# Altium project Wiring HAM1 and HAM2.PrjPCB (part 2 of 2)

## Sheet JMX_PM1.SchDoc: JM1, JM2, JM3 & PM1
size C; Organization: LIGO Laboratory; Address1: California Institute of Technology; Address2: Massachusetts Institute of Technology; DocumentNumber: D0902810; Revision: v11; SheetNumber: 9; SheetTotal: 14; Engineer: J.Kissel/L.Sánchez
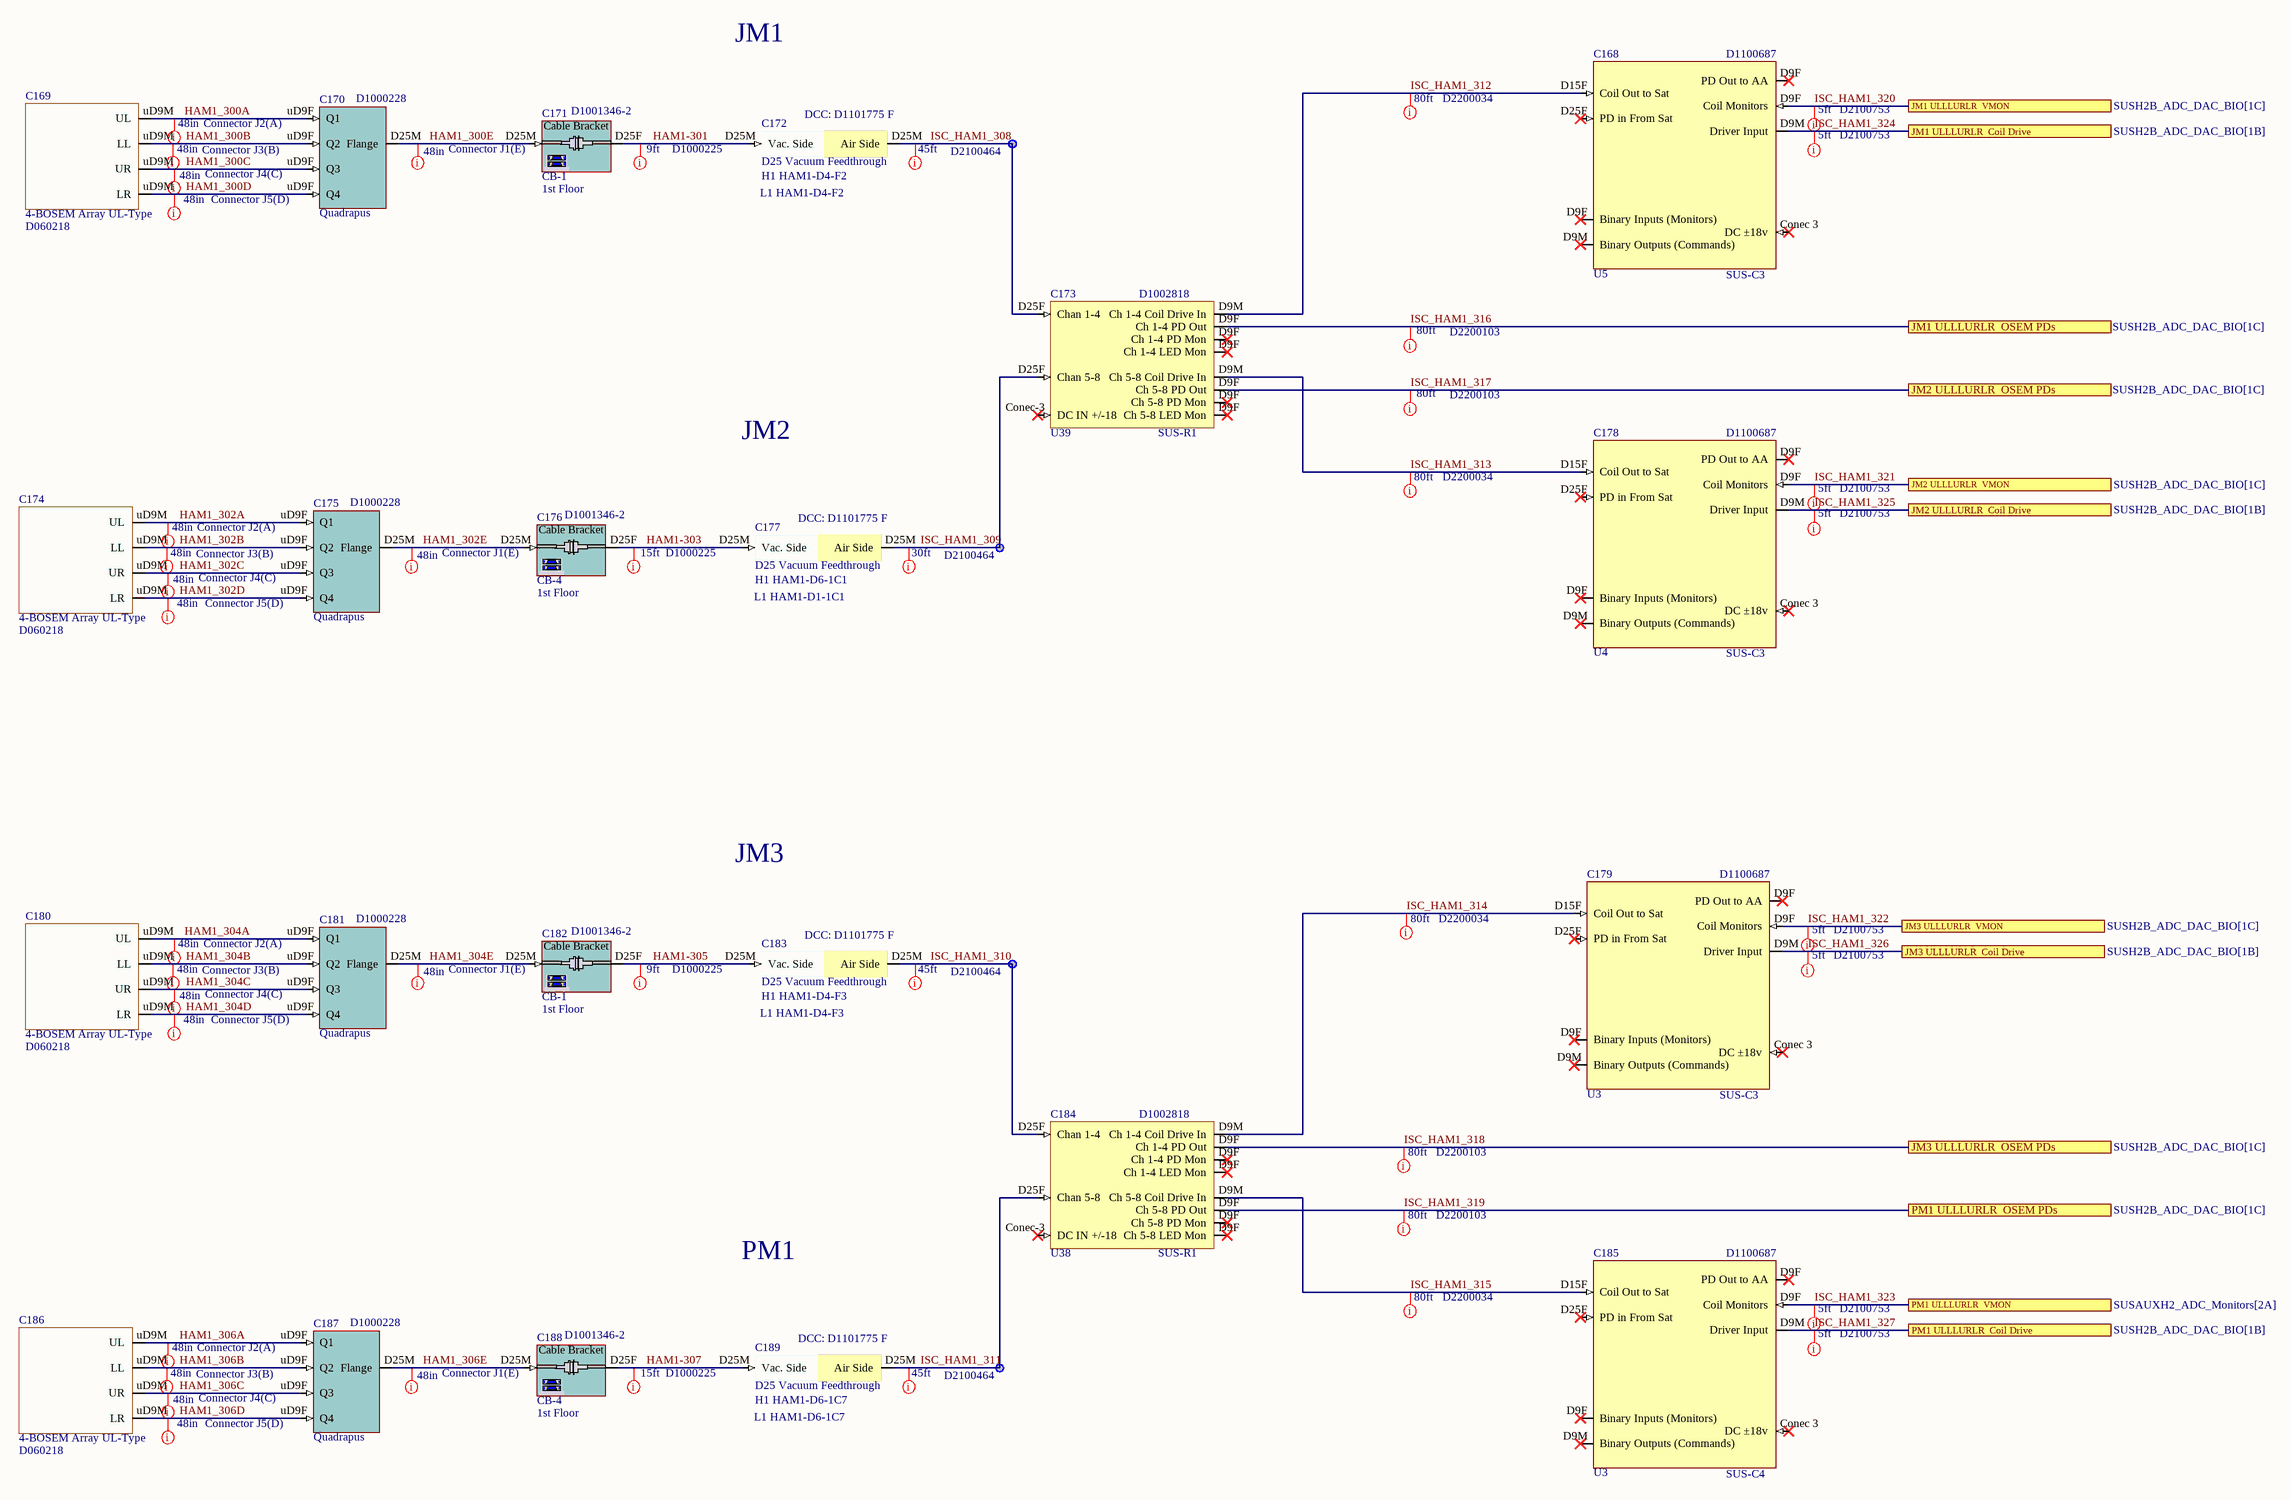
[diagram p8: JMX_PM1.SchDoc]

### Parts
C168  Slot: U5  Rack: SUS-C3  DCC: D1100687  (hidden comment: CD HAM-A D1100687)
C169  4-BOSEM Array UL-Type  DCC: D060218
C170  Quadrapus  DCC: D1000228
C171  Rack: CB-1  Slot: 1st Floor  DCC: D1001346-2  (hidden comment: Cable Bracket)
C172  D25 Vacuum Feedthrough  value H1 HAM1-D4-F2  DCC: D1101775 F
C173  DCC: D1002818  Rack: SUS-R1  Slot: U39  (hidden comment: Satellite Amplifier US D1002818 Dual)
C174  4-BOSEM Array UL-Type  DCC: D060218
C175  Quadrapus  DCC: D1000228
C176  Rack: CB-4  Slot: 1st Floor  DCC: D1001346-2  (hidden comment: Cable Bracket)
C177  D25 Vacuum Feedthrough  value H1 HAM1-D6-1C1  DCC: D1101775 F
C178  Slot: U4  Rack: SUS-C3  DCC: D1100687  (hidden comment: CD HAM-A D1100687)
C179  Slot: U3  Rack: SUS-C3  DCC: D1100687  (hidden comment: CD HAM-A D1100687)
C180  4-BOSEM Array UL-Type  DCC: D060218
C181  Quadrapus  DCC: D1000228
C182  Rack: CB-1  Slot: 1st Floor  DCC: D1001346-2  (hidden comment: Cable Bracket)
C183  D25 Vacuum Feedthrough  value H1 HAM1-D4-F3  DCC: D1101775 F
C184  DCC: D1002818  Rack: SUS-R1  Slot: U38  (hidden comment: Satellite Amplifier US D1002818 Dual)
C185  Slot: U3  Rack: SUS-C4  DCC: D1100687  (hidden comment: CD HAM-A D1100687)
C186  4-BOSEM Array UL-Type  DCC: D060218
C187  Quadrapus  DCC: D1000228
C188  Rack: CB-4  Slot: 1st Floor  DCC: D1001346-2  (hidden comment: Cable Bracket)
C189  D25 Vacuum Feedthrough  value H1 HAM1-D6-1C7  DCC: D1101775 F

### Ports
JM1 ULLLURLR  Coil Drive (see SUSH2B_ADC_DAC_BIO[1B]), JM1 ULLLURLR  OSEM PDs (see SUSH2B_ADC_DAC_BIO[1C]), JM1 ULLLURLR  VMON (see SUSH2B_ADC_DAC_BIO[1C]), JM2 ULLLURLR  Coil Drive (see SUSH2B_ADC_DAC_BIO[1B]), JM2 ULLLURLR  OSEM PDs (see SUSH2B_ADC_DAC_BIO[1C]), JM2 ULLLURLR  VMON (see SUSH2B_ADC_DAC_BIO[1C]), JM3 ULLLURLR  Coil Drive (see SUSH2B_ADC_DAC_BIO[1B]), JM3 ULLLURLR  OSEM PDs (see SUSH2B_ADC_DAC_BIO[1C]), JM3 ULLLURLR  VMON (see SUSH2B_ADC_DAC_BIO[1C]), PM1 ULLLURLR  Coil Drive (see SUSH2B_ADC_DAC_BIO[1B]), PM1 ULLLURLR  OSEM PDs (see SUSH2B_ADC_DAC_BIO[1C]), PM1 ULLLURLR  VMON (see SUSAUXH2_ADC_Monitors[2A])

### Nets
HAM1-301: C171.D25F C172.D25M(Vac._Side)
HAM1-303: C176.D25F C177.D25M(Vac._Side)
HAM1-305: C182.D25F C183.D25M(Vac._Side)
HAM1-307: C188.D25F C189.D25M(Vac._Side)
HAM1_300A: C169.uD9M(UL) C170.uD9F(Q1)
HAM1_300B: C169.uD9M(LL) C170.uD9F(Q2)
HAM1_300C: C169.uD9M(UR) C170.uD9F(Q3)
HAM1_300D: C169.uD9M(LR) C170.uD9F(Q4)
HAM1_300E: C170.D25M(Flange) C171.D25M
HAM1_302A: C174.uD9M(UL) C175.uD9F(Q1)
HAM1_302B: C174.uD9M(LL) C175.uD9F(Q2)
HAM1_302C: C174.uD9M(UR) C175.uD9F(Q3)
HAM1_302D: C174.uD9M(LR) C175.uD9F(Q4)
HAM1_302E: C175.D25M(Flange) C176.D25M
HAM1_304A: C180.uD9M(UL) C181.uD9F(Q1)
HAM1_304B: C180.uD9M(LL) C181.uD9F(Q2)
HAM1_304C: C180.uD9M(UR) C181.uD9F(Q3)
HAM1_304D: C180.uD9M(LR) C181.uD9F(Q4)
HAM1_304E: C181.D25M(Flange) C182.D25M
HAM1_306A: C186.uD9M(UL) C187.uD9F(Q1)
HAM1_306B: C186.uD9M(LL) C187.uD9F(Q2)
HAM1_306C: C186.uD9M(UR) C187.uD9F(Q3)
HAM1_306D: C186.uD9M(LR) C187.uD9F(Q4)
HAM1_306E: C187.D25M(Flange) C188.D25M
ISC_HAM1_308: C172.D25M(Air_Side) C173.D25F(Chan_1-4)
ISC_HAM1_309: C173.D25F(Chan_5-8) C177.D25M(Air_Side)
ISC_HAM1_310: C183.D25M(Air_Side) C184.D25F(Chan_1-4)
ISC_HAM1_311: C184.D25F(Chan_5-8) C189.D25M(Air_Side)
ISC_HAM1_312: C168.D15F(Coil_Out_to_Sat) C173.D9M(Ch_1-4_Coil_Drive_In)
ISC_HAM1_313: C173.D9M(Ch_5-8_Coil_Drive_In) C178.D15F(Coil_Out_to_Sat)
ISC_HAM1_314: C179.D15F(Coil_Out_to_Sat) C184.D9M(Ch_1-4_Coil_Drive_In)
ISC_HAM1_315: C184.D9M(Ch_5-8_Coil_Drive_In) C185.D15F(Coil_Out_to_Sat)
ISC_HAM1_316: C173.D9F(Ch_1-4_PD_Out) ; port JM1 ULLLURLR  OSEM PDs
ISC_HAM1_317: C173.D9F(Ch_5-8_PD_Out) ; port JM2 ULLLURLR  OSEM PDs
ISC_HAM1_318: C184.D9F(Ch_1-4_PD_Out) ; port JM3 ULLLURLR  OSEM PDs
ISC_HAM1_319: C184.D9F(Ch_5-8_PD_Out) ; port PM1 ULLLURLR  OSEM PDs
ISC_HAM1_320: C168.D9F(PD_Out_to_AA) ; port JM1 ULLLURLR  VMON
ISC_HAM1_321: C178.D9F(PD_Out_to_AA) ; port JM2 ULLLURLR  VMON
ISC_HAM1_322: C179.D9F(PD_Out_to_AA) ; port JM3 ULLLURLR  VMON
ISC_HAM1_323: C185.D9F(PD_Out_to_AA) ; port PM1 ULLLURLR  VMON
ISC_HAM1_324: C168.D9M(Binary_Outputs_(Commands)) ; port JM1 ULLLURLR  Coil Drive
ISC_HAM1_325: C178.D9M(Binary_Outputs_(Commands)) ; port JM2 ULLLURLR  Coil Drive
ISC_HAM1_326: C179.D9M(Binary_Outputs_(Commands)) ; port JM3 ULLLURLR  Coil Drive
ISC_HAM1_327: C185.D9M(Binary_Outputs_(Commands)) ; port PM1 ULLLURLR  Coil Drive

Not connected (* = marked no-connect by the designer): C168 Conec 3(DC_±18v)* D25F(PD_in_From_Sat)*; C173 Conec-3(DC_IN_+/-18)*; C178 Conec 3(DC_±18v)* D25F(PD_in_From_Sat)*; C179 Conec 3(DC_±18v)* D25F(PD_in_From_Sat)*; C184 Conec-3(DC_IN_+/-18)*; C185 Conec 3(DC_±18v)* D25F(PD_in_From_Sat)*

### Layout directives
Length: 45ft; DCC: D2100464: ISC_HAM1_308, ISC_HAM1_310, ISC_HAM1_311
Length: 5ft; DCC: D2100753: ISC_HAM1_320, ISC_HAM1_321, ISC_HAM1_322, ISC_HAM1_323, ISC_HAM1_324, ISC_HAM1_325, ISC_HAM1_326, ISC_HAM1_327
Length: 48in; DCC: Connector J5(D): HAM1_300D, HAM1_302D, HAM1_304D, HAM1_306D
Length: 48in; DCC: Connector J4(C): HAM1_300C, HAM1_302C, HAM1_304C, HAM1_306C
Length: 48in; DCC: Connector J3(B): HAM1_300B, HAM1_302B, HAM1_304B, HAM1_306B
Length: 48in; DCC: Connector J2(A): HAM1_300A, HAM1_302A, HAM1_304A, HAM1_306A
Length: 80ft; DCC: D2200034: ISC_HAM1_312, ISC_HAM1_313, ISC_HAM1_314, ISC_HAM1_315
Length: 48in; DCC: Connector J1(E): HAM1_300E, HAM1_302E, HAM1_304E, HAM1_306E
Length: 9ft; DCC: D1000225: HAM1-301, HAM1-305
Length: 30ft; DCC: D2100464: ISC_HAM1_309
Length: 15ft; DCC: D1000225: HAM1-303, HAM1-307
Length: 80ft; DCC: D2200103: ISC_HAM1_316, ISC_HAM1_317, ISC_HAM1_318, ISC_HAM1_319

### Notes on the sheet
- JM1
- (near C172) L1 HAM1-D4-F2
- JM2
- (near C177) L1 HAM1-D1-1C1
- JM3
- (near C183) L1 HAM1-D4-F3
- PM1
- (near C189) L1 HAM1-D6-1C7

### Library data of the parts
C168 C178 C179 C185 = CD HAM-A D1100687: System: SUS; Serial: Sxxxxxxx
C169 C174 C180 C186 = 4-BOSEM Array UL-Type: Rack: R?; Slot: U?; Serial: Sxxxxxxx; System: SUS
C170 C175 C181 C187 = D1000228 D25 Quadrapus: Slot: U?; Rack: R?; Serial: Sxxxxxxx; System: SUS
C171 C176 C182 C188 = D1001346-2 1st Cable Bracket: D1001346-2 1/2 Cable Bracket for HAM Tables; Serial: Sxxxxxxx; System: SUS
C172 = VacFeedD25: Serial: Sxxxxxxx; System: ISC; Rack: HAM1; Slot: D4-F2
C173 C184 = Satellite Amplifier US D1002818: Serial: Sxxxxxxx
C177 = VacFeedD25: Serial: Sxxxxxxx; System: ISC; Rack: HAM1; Slot: D1-1C3
C183 = VacFeedD25: Serial: Sxxxxxxx; System: ISC; Rack: HAM1; Slot: D4-F3
C189 = VacFeedD25: Serial: Sxxxxxxx; System: ISC; Rack: HAM1; Slot: D4-F1

## Sheet SUSH2A_ADC_DAC_BIO.SchDoc: SUSH2A_ADC_DAC_BIO
size C; Organization: LIGO Laboratory; Address1: California Institute of Technology; Address2: Massachusetts Institute of Technology; DocumentNumber: D0902810; Revision: v11; SheetNumber: 10; SheetTotal: 14; Engineer: J.Kissel/L.Sánchez
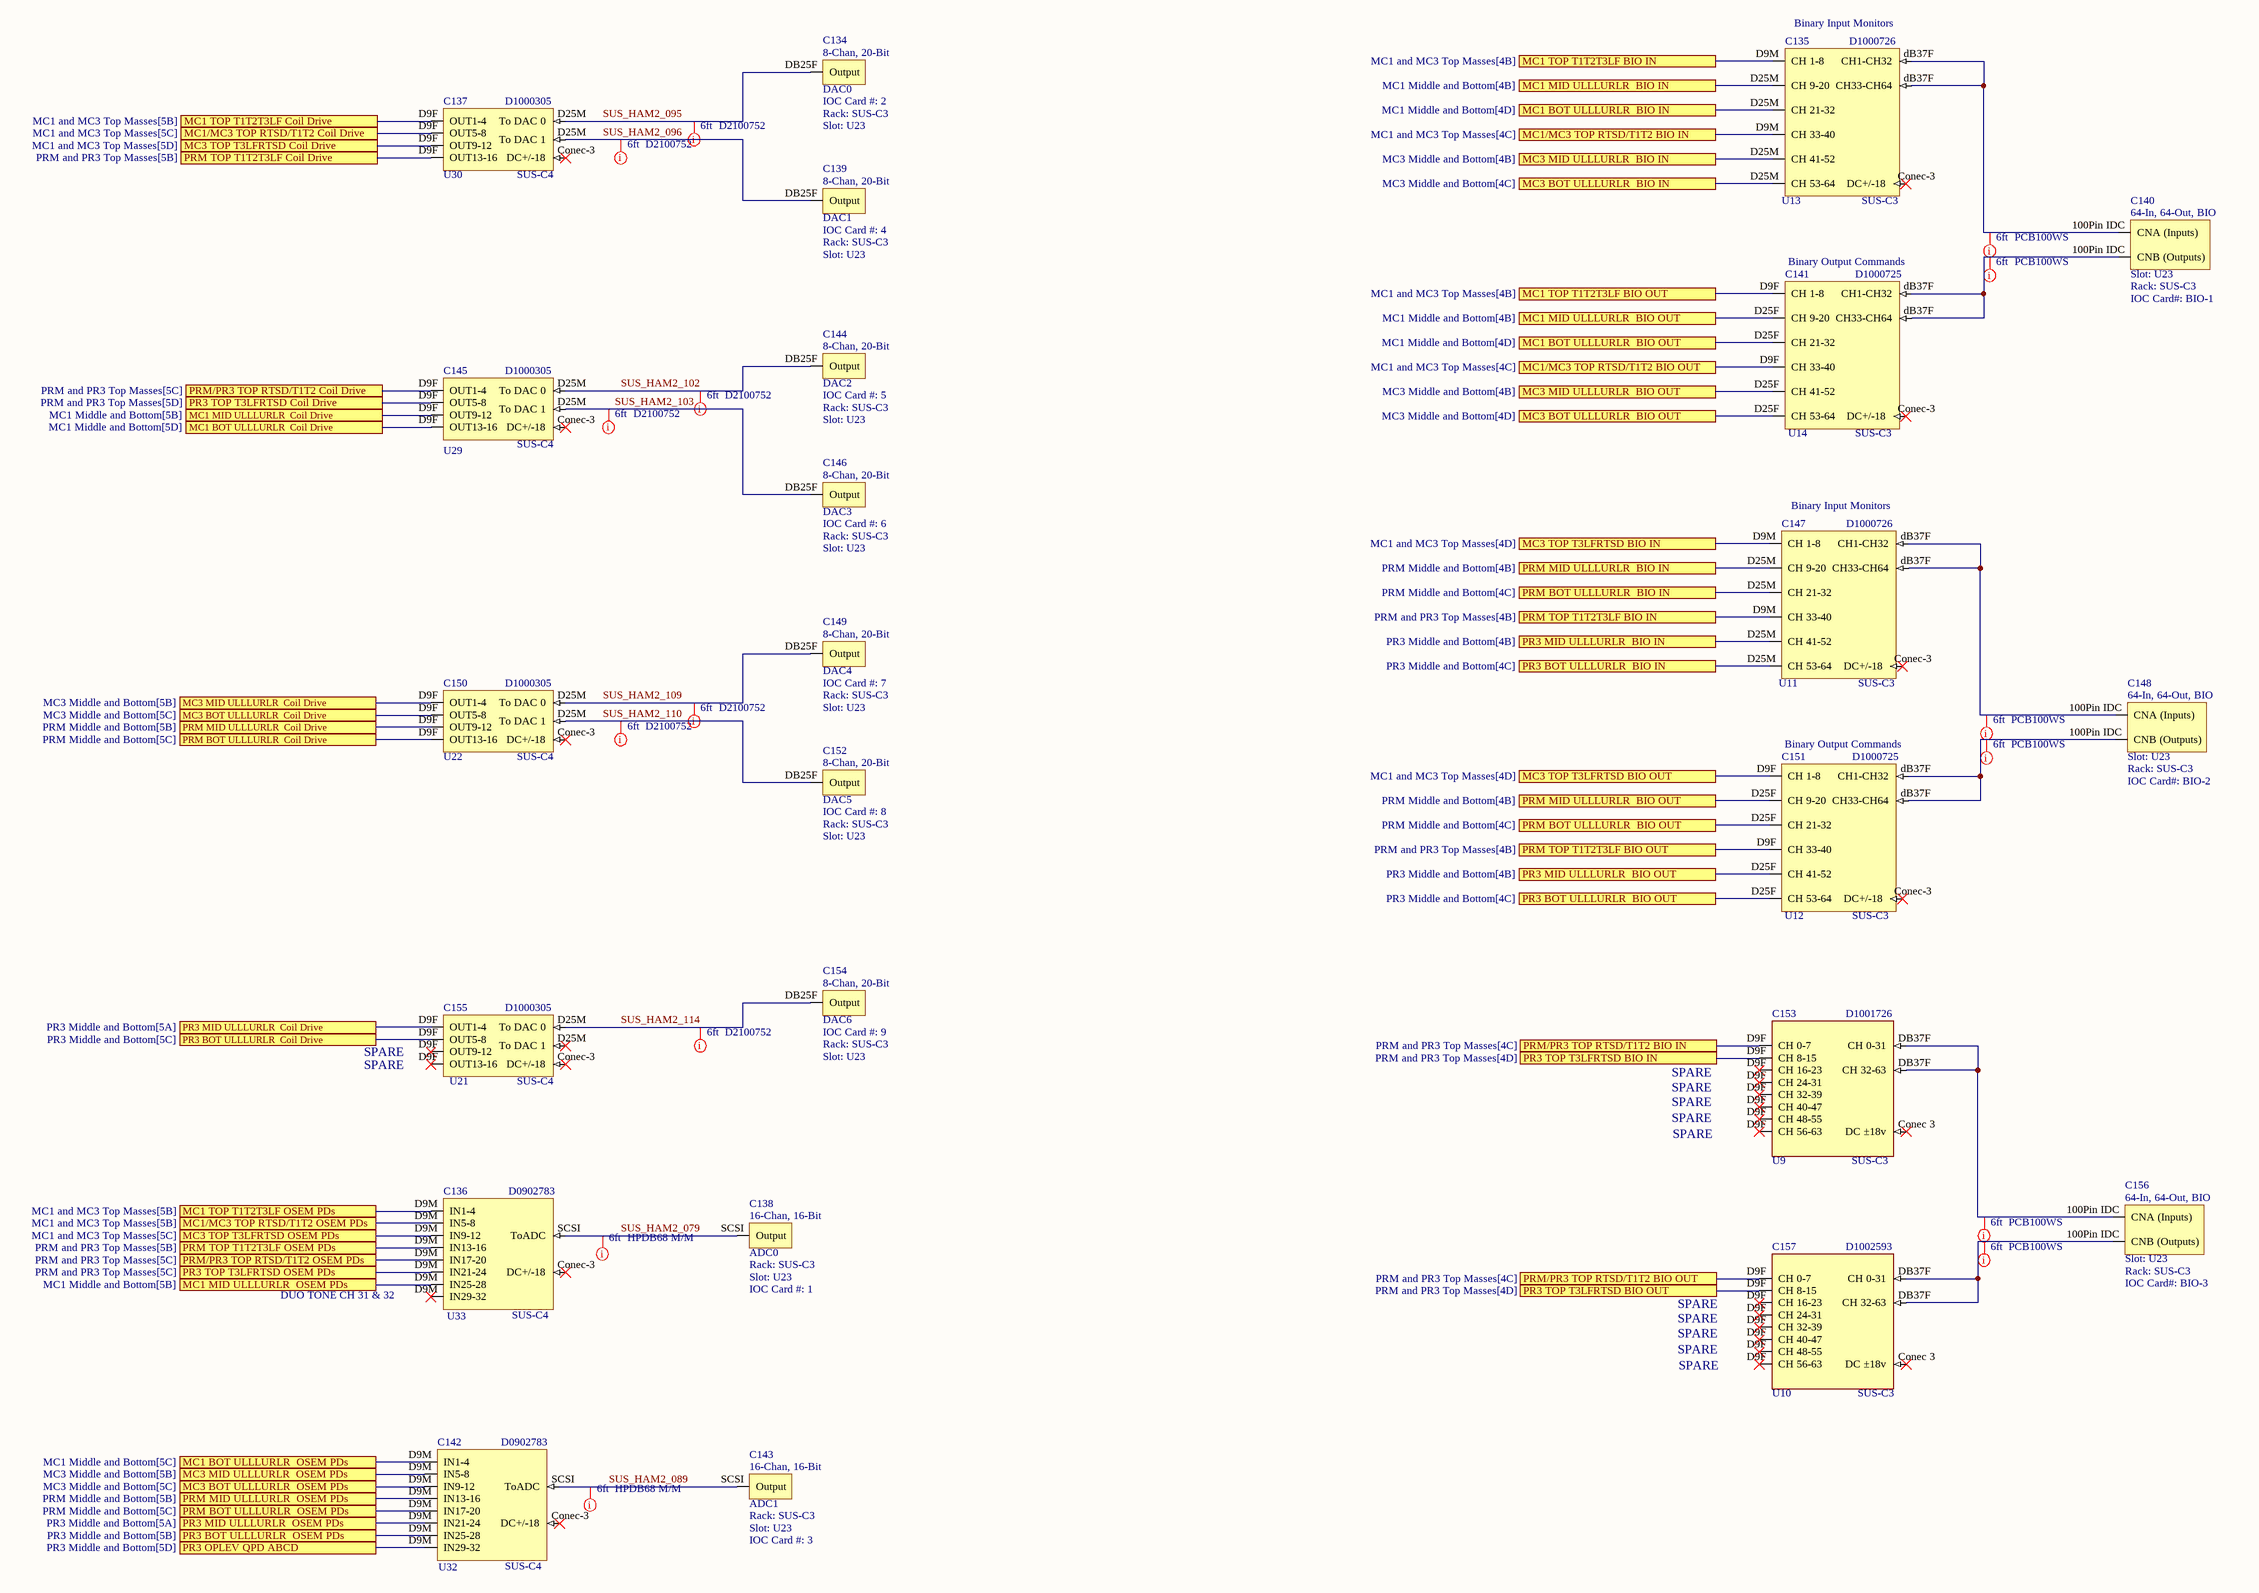
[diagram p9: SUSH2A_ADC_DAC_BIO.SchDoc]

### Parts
C134  DAC0  IOC Card #: 2  Rack: SUS-C3  Slot: U23
C135  Parameter: Binary Input Monitors  Slot: U13  Rack: SUS-C3  DCC: D1000726  (hidden comment: BI D1000726 Monitors)
C136  DCC: D0902783  Rack: SUS-C4  Slot: U33  (hidden comment: AA D0902783 8xD9)
C137  Rack: SUS-C4  Slot: U30  DCC: D1000305  (hidden comment: AI D1000305 4xD9 18_20_Bit)
C138  ADC0  Rack: SUS-C3  Slot: U23  IOC Card #: 1
C139  DAC1  IOC Card #: 4  Rack: SUS-C3  Slot: U23
C140  Slot: U23  Rack: SUS-C3  IOC Card#: BIO-1  (hidden comment: BIO Contec Card 64Ix64O)
C141  Parameter: Binary Output Commands  Slot: U14  Rack: SUS-C3  DCC: D1000725  (hidden comment: BO D1000725 Commands)
C142  DCC: D0902783  Rack: SUS-C4  Slot: U32  (hidden comment: AA D0902783 8xD9)
C143  ADC1  Rack: SUS-C3  Slot: U23  IOC Card #: 3
C144  DAC2  IOC Card #: 5  Rack: SUS-C3  Slot: U23
C145  Rack: SUS-C4  Slot: U29  DCC: D1000305  (hidden comment: AI D1000305 4xD9 18_20_Bit)
C146  DAC3  IOC Card #: 6  Rack: SUS-C3  Slot: U23
C147  Parameter: Binary Input Monitors  Slot: U11  Rack: SUS-C3  DCC: D1000726  (hidden comment: BI D1000726 Monitors)
C148  Slot: U23  Rack: SUS-C3  IOC Card#: BIO-2  (hidden comment: BIO Contec Card 64Ix64O)
C149  DAC4  IOC Card #: 7  Rack: SUS-C3  Slot: U23
C150  Rack: SUS-C4  Slot: U22  DCC: D1000305  (hidden comment: AI D1000305 4xD9 18_20_Bit)
C151  Parameter: Binary Output Commands  Slot: U12  Rack: SUS-C3  DCC: D1000725  (hidden comment: BO D1000725 Commands)
C152  DAC5  IOC Card #: 8  Rack: SUS-C3  Slot: U23
C153  Slot: U9  Rack: SUS-C3  DCC: D1001726  (hidden comment: BI D1001726 Monitors_8xDB9)
C154  DAC6  IOC Card #: 9  Rack: SUS-C3  Slot: U23
C155  Rack: SUS-C4  Slot: U21  DCC: D1000305  (hidden comment: AI D1000305 4xD9 18_20_Bit)
C156  Slot: U23  Rack: SUS-C3  IOC Card#: BIO-3  (hidden comment: BIO Contec Card 64Ix64O)
C157  Slot: U10  Rack: SUS-C3  DCC: D1002593  (hidden comment: BO D1002593 Commands_8xDB9)

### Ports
MC1 BOT ULLLURLR  BIO IN (see MC1 Middle and Bottom[4D]), MC1 BOT ULLLURLR  BIO OUT (see MC1 Middle and Bottom[4D]), MC1 BOT ULLLURLR  Coil Drive (see MC1 Middle and Bottom[5D]), MC1 BOT ULLLURLR  OSEM PDs (see MC1 Middle and Bottom[5C]), MC1 MID ULLLURLR  BIO IN (see MC1 Middle and Bottom[4B]), MC1 MID ULLLURLR  BIO OUT (see MC1 Middle and Bottom[4B]), MC1 MID ULLLURLR  Coil Drive (see MC1 Middle and Bottom[5B]), MC1 MID ULLLURLR  OSEM PDs (see MC1 Middle and Bottom[5B]), MC1 TOP T1T2T3LF BIO IN (see MC1 and MC3 Top Masses[4B]), MC1 TOP T1T2T3LF BIO OUT (see MC1 and MC3 Top Masses[4B]), MC1 TOP T1T2T3LF Coil Drive (see MC1 and MC3 Top Masses[5B]), MC1 TOP T1T2T3LF OSEM PDs (see MC1 and MC3 Top Masses[5B]), MC1/MC3 TOP RTSD/T1T2 BIO IN (see MC1 and MC3 Top Masses[4C]), MC1/MC3 TOP RTSD/T1T2 BIO OUT (see MC1 and MC3 Top Masses[4C]), MC1/MC3 TOP RTSD/T1T2 Coil Drive (see MC1 and MC3 Top Masses[5C]), MC1/MC3 TOP RTSD/T1T2 OSEM PDs (see MC1 and MC3 Top Masses[5B]), MC3 BOT ULLLURLR  BIO IN (see MC3 Middle and Bottom[4C]), MC3 BOT ULLLURLR  BIO OUT (see MC3 Middle and Bottom[4D]), MC3 BOT ULLLURLR  Coil Drive (see MC3 Middle and Bottom[5C]), MC3 BOT ULLLURLR  OSEM PDs (see MC3 Middle and Bottom[5C]), MC3 MID ULLLURLR  BIO IN (see MC3 Middle and Bottom[4B]), MC3 MID ULLLURLR  BIO OUT (see MC3 Middle and Bottom[4B]), MC3 MID ULLLURLR  Coil Drive (see MC3 Middle and Bottom[5B]), MC3 MID ULLLURLR  OSEM PDs (see MC3 Middle and Bottom[5B]), MC3 TOP T3LFRTSD BIO IN (see MC1 and MC3 Top Masses[4D]), MC3 TOP T3LFRTSD BIO OUT (see MC1 and MC3 Top Masses[4D]), MC3 TOP T3LFRTSD Coil Drive (see MC1 and MC3 Top Masses[5D]), MC3 TOP T3LFRTSD OSEM PDs (see MC1 and MC3 Top Masses[5C]), PR3 BOT ULLLURLR  BIO IN (see PR3 Middle and Bottom[4C]), PR3 BOT ULLLURLR  BIO OUT (see PR3 Middle and Bottom[4C]), PR3 BOT ULLLURLR  Coil Drive (see PR3 Middle and Bottom[5C]), PR3 BOT ULLLURLR  OSEM PDs (see PR3 Middle and Bottom[5B]), PR3 MID ULLLURLR  BIO IN (see PR3 Middle and Bottom[4B]), PR3 MID ULLLURLR  BIO OUT (see PR3 Middle and Bottom[4B]), PR3 MID ULLLURLR  Coil Drive (see PR3 Middle and Bottom[5A]), PR3 MID ULLLURLR  OSEM PDs (see PR3 Middle and Bottom[5A]), PR3 OPLEV QPD ABCD (see PR3 Middle and Bottom[5D]), PR3 TOP T3LFRTSD BIO IN (see PRM and PR3 Top Masses[4D]), PR3 TOP T3LFRTSD BIO OUT (see PRM and PR3 Top Masses[4D]), PR3 TOP T3LFRTSD Coil Drive (see PRM and PR3 Top Masses[5D]), PR3 TOP T3LFRTSD OSEM PDs (see PRM and PR3 Top Masses[5C]), PRM BOT ULLLURLR  BIO IN (see PRM Middle and Bottom[4C]), PRM BOT ULLLURLR  BIO OUT (see PRM Middle and Bottom[4C]), PRM BOT ULLLURLR  Coil Drive (see PRM Middle and Bottom[5C]), PRM BOT ULLLURLR  OSEM PDs (see PRM Middle and Bottom[5C]), PRM MID ULLLURLR  BIO IN (see PRM Middle and Bottom[4B]), PRM MID ULLLURLR  BIO OUT (see PRM Middle and Bottom[4B]), PRM MID ULLLURLR  Coil Drive (see PRM Middle and Bottom[5B]), PRM MID ULLLURLR  OSEM PDs (see PRM Middle and Bottom[5B]), PRM TOP T1T2T3LF BIO IN (see PRM and PR3 Top Masses[4B]), PRM TOP T1T2T3LF BIO OUT (see PRM and PR3 Top Masses[4B]), PRM TOP T1T2T3LF Coil Drive (see PRM and PR3 Top Masses[5B]), PRM TOP T1T2T3LF OSEM PDs (see PRM and PR3 Top Masses[5B]), PRM/PR3 TOP RTSD/T1T2 BIO IN (see PRM and PR3 Top Masses[4C]), PRM/PR3 TOP RTSD/T1T2 BIO OUT (see PRM and PR3 Top Masses[4C]), PRM/PR3 TOP RTSD/T1T2 Coil Drive (see PRM and PR3 Top Masses[5C]), PRM/PR3 TOP RTSD/T1T2 OSEM PDs (see PRM and PR3 Top Masses[5C])

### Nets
SUS_ OPLEV_PR3_AA: C142.D9M(IN29-32) ; port PR3 OPLEV QPD ABCD
SUS_HAM2_043: C135.D9M(CH_1-8) ; port MC1 TOP T1T2T3LF BIO IN
SUS_HAM2_044: C141.D9F(CH_1-8) ; port MC1 TOP T1T2T3LF BIO OUT
SUS_HAM2_045: C135.D9M(CH_33-40) ; port MC1/MC3 TOP RTSD/T1T2 BIO IN
SUS_HAM2_046: C141.D9F(CH_33-40) ; port MC1/MC3 TOP RTSD/T1T2 BIO OUT
SUS_HAM2_047: C147.D9M(CH_1-8) ; port MC3 TOP T3LFRTSD BIO IN
SUS_HAM2_048: C151.D9F(CH_1-8) ; port MC3 TOP T3LFRTSD BIO OUT
SUS_HAM2_049: C147.D9M(CH_33-40) ; port PRM TOP T1T2T3LF BIO IN
SUS_HAM2_050: C151.D9F(CH_33-40) ; port PRM TOP T1T2T3LF BIO OUT
SUS_HAM2_051: C153.D9F(CH_0-7) ; port PRM/PR3 TOP RTSD/T1T2 BIO IN
SUS_HAM2_052: C157.D9F(CH_0-7) ; port PRM/PR3 TOP RTSD/T1T2 BIO OUT
SUS_HAM2_053: C153.D9F(CH_8-15) ; port PR3 TOP T3LFRTSD BIO IN
SUS_HAM2_054: C157.D9F(CH_8-15) ; port PR3 TOP T3LFRTSD BIO OUT
SUS_HAM2_055: C135.D25M(CH_9-20) ; port MC1 MID ULLLURLR  BIO IN
SUS_HAM2_056: C141.D25F(CH_9-20) ; port MC1 MID ULLLURLR  BIO OUT
SUS_HAM2_057: C135.D25M(CH_21-32) ; port MC1 BOT ULLLURLR  BIO IN
SUS_HAM2_058: C141.D25F(CH_21-32) ; port MC1 BOT ULLLURLR  BIO OUT
SUS_HAM2_059: C135.D25M(CH_41-52) ; port MC3 MID ULLLURLR  BIO IN
SUS_HAM2_060: C141.D25F(CH_41-52) ; port MC3 MID ULLLURLR  BIO OUT
SUS_HAM2_061: C135.D25M(CH_53-64) ; port MC3 BOT ULLLURLR  BIO IN
SUS_HAM2_062: C141.D25F(CH_53-64) ; port MC3 BOT ULLLURLR  BIO OUT
SUS_HAM2_063: C147.D25M(CH_9-20) ; port PRM MID ULLLURLR  BIO IN
SUS_HAM2_064: C151.D25F(CH_9-20) ; port PRM MID ULLLURLR  BIO OUT
SUS_HAM2_065: C147.D25M(CH_21-32) ; port PRM BOT ULLLURLR  BIO IN
SUS_HAM2_066: C151.D25F(CH_21-32) ; port PRM BOT ULLLURLR  BIO OUT
SUS_HAM2_067: C147.D25M(CH_41-52) ; port PR3 MID ULLLURLR  BIO IN
SUS_HAM2_068: C151.D25F(CH_41-52) ; port PR3 MID ULLLURLR  BIO OUT
SUS_HAM2_069: C147.D25M(CH_53-64) ; port PR3 BOT ULLLURLR  BIO IN
SUS_HAM2_070: C151.D25F(CH_53-64) ; port PR3 BOT ULLLURLR  BIO OUT
SUS_HAM2_071: C136.D9M(IN1-4) ; port MC1 TOP T1T2T3LF OSEM PDs
SUS_HAM2_072: C136.D9M(IN5-8) ; port MC1/MC3 TOP RTSD/T1T2 OSEM PDs
SUS_HAM2_073: C136.D9M(IN9-12) ; port MC3 TOP T3LFRTSD OSEM PDs
SUS_HAM2_074: C136.D9M(IN13-16) ; port PRM TOP T1T2T3LF OSEM PDs
SUS_HAM2_075: C136.D9M(IN17-20) ; port PRM/PR3 TOP RTSD/T1T2 OSEM PDs
SUS_HAM2_076: C136.D9M(IN21-24) ; port PR3 TOP T3LFRTSD OSEM PDs
SUS_HAM2_077: C136.D9M(IN25-28) ; port MC1 MID ULLLURLR  OSEM PDs
SUS_HAM2_079: C136.SCSI(ToADC) C138.SCSI(Output)
SUS_HAM2_081: C142.D9M(IN1-4) ; port MC1 BOT ULLLURLR  OSEM PDs
SUS_HAM2_082: C142.D9M(IN5-8) ; port MC3 MID ULLLURLR  OSEM PDs
SUS_HAM2_083: C142.D9M(IN9-12) ; port MC3 BOT ULLLURLR  OSEM PDs
SUS_HAM2_084: C142.D9M(IN13-16) ; port PRM MID ULLLURLR  OSEM PDs
SUS_HAM2_085: C142.D9M(IN17-20) ; port PRM BOT ULLLURLR  OSEM PDs
SUS_HAM2_086: C142.D9M(IN21-24) ; port PR3 MID ULLLURLR  OSEM PDs
SUS_HAM2_087: C142.D9M(IN25-28) ; port PR3 BOT ULLLURLR  OSEM PDs
SUS_HAM2_089: C142.SCSI(ToADC) C143.SCSI(Output)
SUS_HAM2_091: C137.D9F(OUT1-4) ; port MC1 TOP T1T2T3LF Coil Drive
SUS_HAM2_092: C137.D9F(OUT5-8) ; port MC1/MC3 TOP RTSD/T1T2 Coil Drive
SUS_HAM2_093: C137.D9F(OUT9-12) ; port MC3 TOP T3LFRTSD Coil Drive
SUS_HAM2_094: C137.D9F(OUT13-16) ; port PRM TOP T1T2T3LF Coil Drive
SUS_HAM2_095: C134.DB25F(Output) C137.D25M(To_DAC_0)
SUS_HAM2_096: C137.D25M(To_DAC_1) C139.DB25F(Output)
SUS_HAM2_098: C145.D9F(OUT1-4) ; port PRM/PR3 TOP RTSD/T1T2 Coil Drive
SUS_HAM2_099: C145.D9F(OUT5-8) ; port PR3 TOP T3LFRTSD Coil Drive
SUS_HAM2_100: C145.D9F(OUT9-12) ; port MC1 MID ULLLURLR  Coil Drive
SUS_HAM2_101: C145.D9F(OUT13-16) ; port MC1 BOT ULLLURLR  Coil Drive
SUS_HAM2_102: C144.DB25F(Output) C145.D25M(To_DAC_0)
SUS_HAM2_103: C145.D25M(To_DAC_1) C146.DB25F(Output)
SUS_HAM2_105: C150.D9F(OUT1-4) ; port MC3 MID ULLLURLR  Coil Drive
SUS_HAM2_106: C150.D9F(OUT5-8) ; port MC3 BOT ULLLURLR  Coil Drive
SUS_HAM2_107: C150.D9F(OUT9-12) ; port PRM MID ULLLURLR  Coil Drive
SUS_HAM2_108: C150.D9F(OUT13-16) ; port PRM BOT ULLLURLR  Coil Drive
SUS_HAM2_109: C149.DB25F(Output) C150.D25M(To_DAC_0)
SUS_HAM2_110: C150.D25M(To_DAC_1) C152.DB25F(Output)
SUS_HAM2_112: C155.D9F(OUT1-4) ; port PR3 MID ULLLURLR  Coil Drive
SUS_HAM2_113: C155.D9F(OUT5-8) ; port PR3 BOT ULLLURLR  Coil Drive
SUS_HAM2_114: C154.DB25F(Output) C155.D25M(To_DAC_0)
NetC135_dB37F: C135.dB37F(CH1-CH32) C140.100Pin_IDC(CNA_(Inputs))
NetC140_100Pin IDC: C140.100Pin_IDC(CNB_(Outputs)) C141.dB37F(CH1-CH32)
NetC147_dB37F: C147.dB37F(CH1-CH32) C148.100Pin_IDC(CNA_(Inputs))
NetC148_100Pin IDC: C148.100Pin_IDC(CNB_(Outputs)) C151.dB37F(CH1-CH32)
NetC153_DB37F: C153.DB37F(CH_0-31) C156.100Pin_IDC(CNA_(Inputs))
NetC156_100Pin IDC: C156.100Pin_IDC(CNB_(Outputs)) C157.DB37F(CH_0-31)

Not connected (* = marked no-connect by the designer): C135 Conec-3(DC+/-18)*; C136 Conec-3(DC+/-18)*; C137 Conec-3(DC+/-18)*; C141 Conec-3(DC+/-18)*; C142 Conec-3(DC+/-18)*; C145 Conec-3(DC+/-18)*; C147 Conec-3(DC+/-18)*; C150 Conec-3(DC+/-18)*; C151 Conec-3(DC+/-18)*; C153 Conec 3(DC_±18v)*; C155 Conec-3(DC+/-18)*; C157 Conec 3(DC_±18v)*

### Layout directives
Length: 6ft; DCC: HPDB68 M/M: SUS_HAM2_079, SUS_HAM2_089
Length: 6ft; DCC: D2100752: SUS_HAM2_095, SUS_HAM2_096, SUS_HAM2_102, SUS_HAM2_103, SUS_HAM2_109, SUS_HAM2_110, SUS_HAM2_114
Length: 6ft; DCC: PCB100WS: NetC135_dB37F, NetC140_100Pin IDC, NetC147_dB37F, NetC148_100Pin IDC, NetC153_DB37F, NetC156_100Pin IDC

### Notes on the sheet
- (near C155) SPARE
- SPARE
- DUO TONE CH 31 & 32

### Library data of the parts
C134 C139 C144 C146 C149 C152 C154 = DAC-20: 8 Chan, 20 Bit DAC
C135 C147 = BI D1000726 Monitors: Serial: Sxxxxxxx; System: SUS
C136 C142 = AA D0902783 8xD9: Serial: Sxxxxxxx; System: SUS
C137 C145 C150 C155 = AI D1000305 4xD9 18_20_Bit: System: SUS; Serial: Sxxxxxxx
C138 C143 = ADC-16: 16 Chan, 16 Bit ADC
C140 C148 C156 = BIO Contec Card 64Ix64O: System: SUS
C141 C151 = BO D1000725 Commands: Serial: Sxxxxxxx; System: SUS
C153 = BI D1001726 Monitors_8xDB9: Serial: Sxxxxxxx; System: SUS
C157 = BO D1002593 Commands_8xDB9: Serial: Sxxxxxxx; System: SUS

## Sheet SUSH2B_ADC_DAC_BIO.SchDoc: SUSH2B_ADC_DAC_BIO
size C; Organization: LIGO Laboratory; Address1: California Institute of Technology; Address2: Massachusetts Institute of Technology; DocumentNumber: D0902810; Revision: v11; SheetNumber: 11; SheetTotal: 14; Engineer: J.Kissel/L.Sánchez
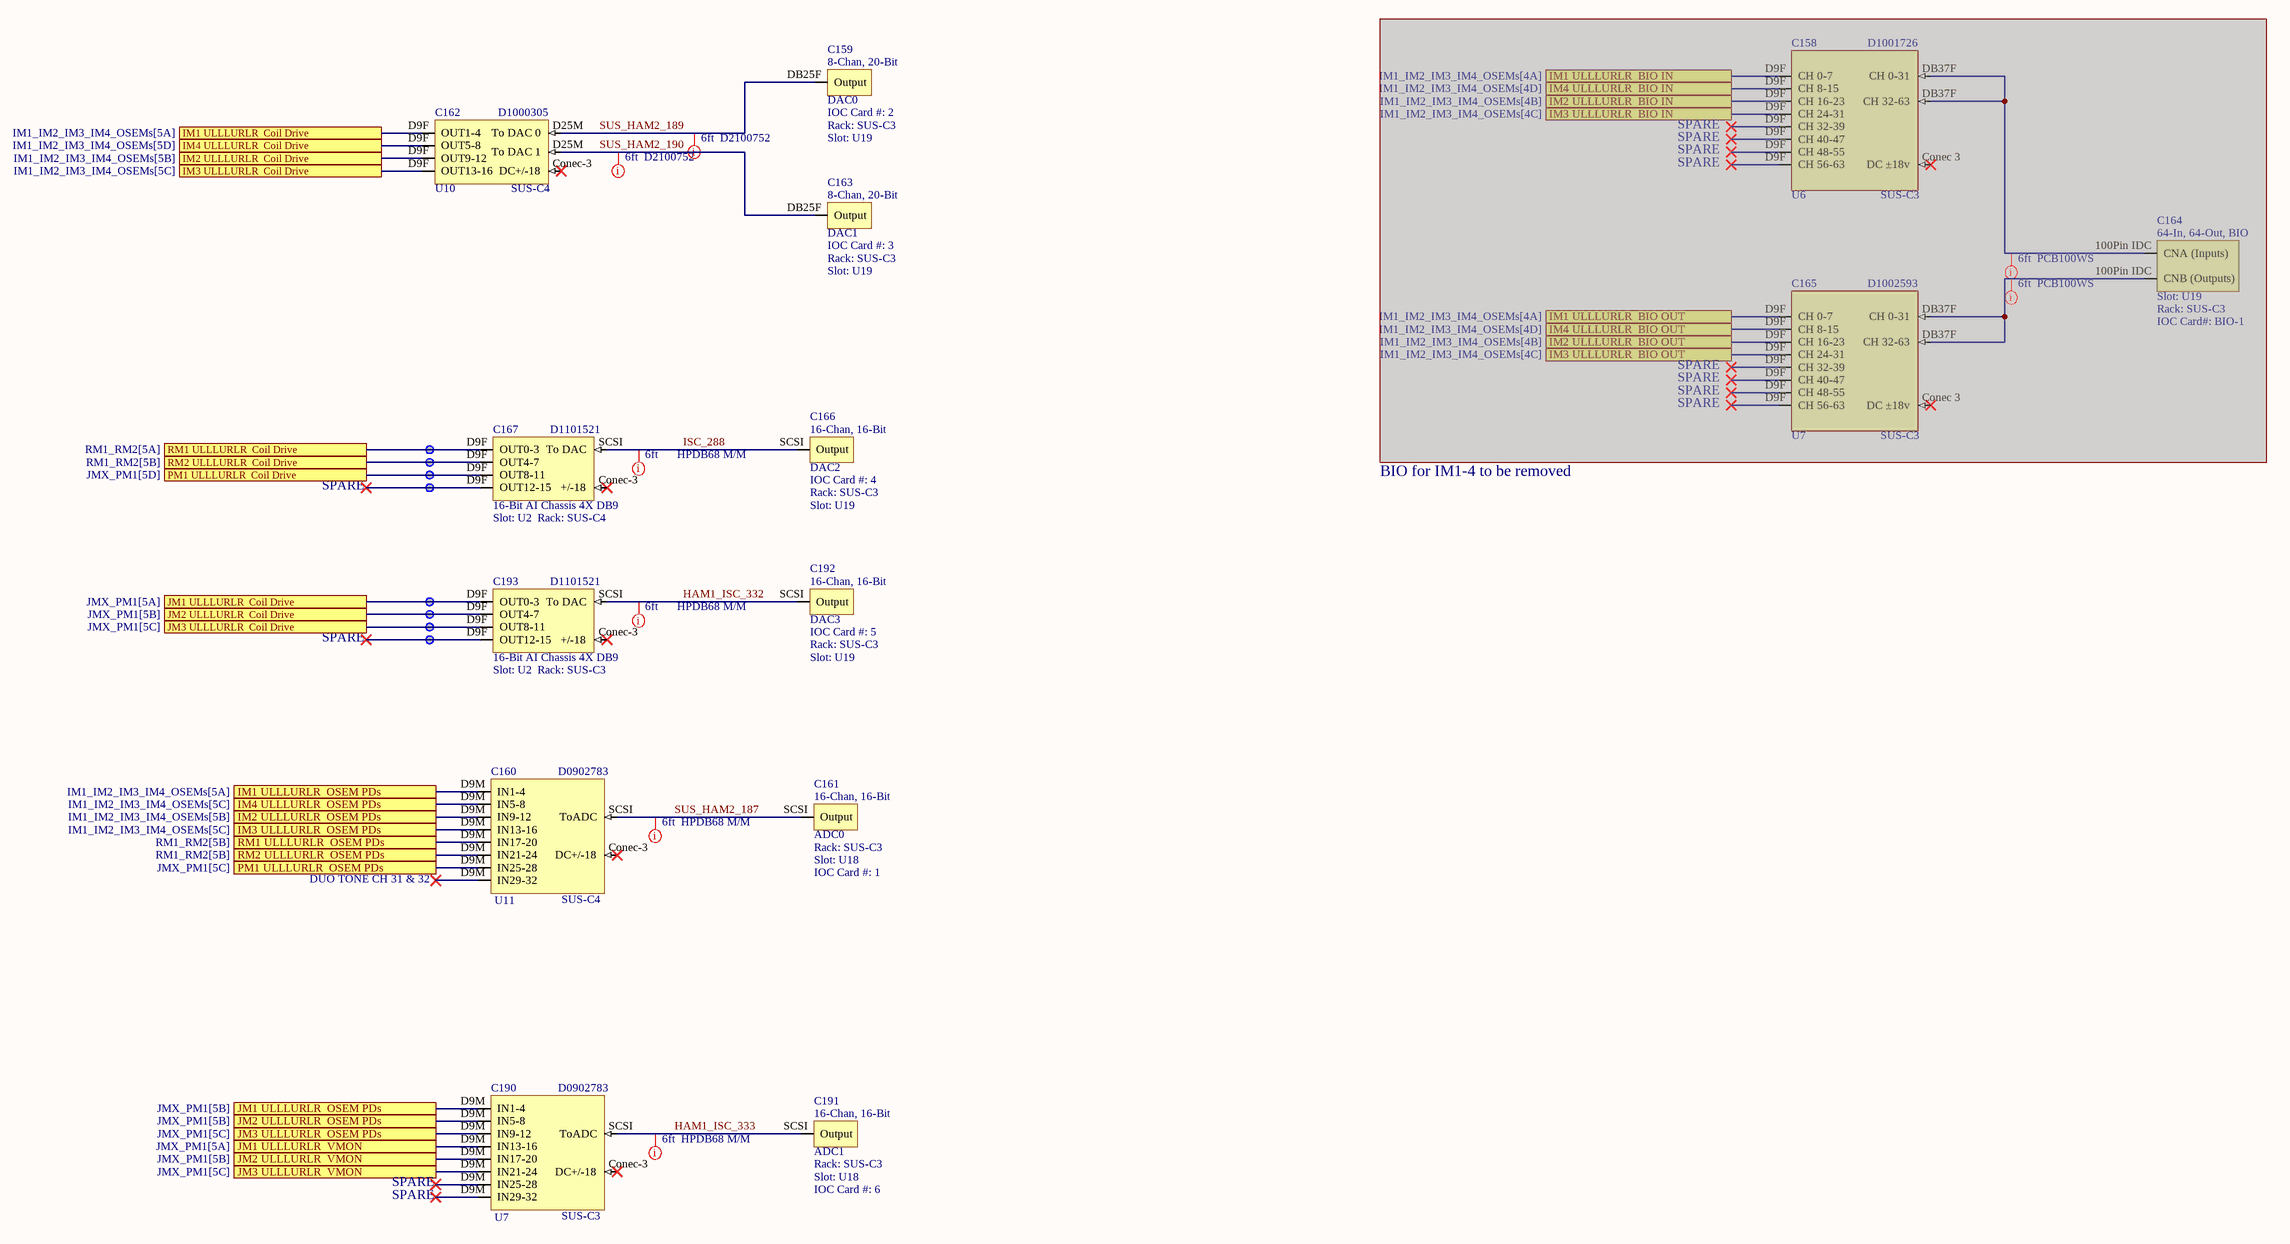
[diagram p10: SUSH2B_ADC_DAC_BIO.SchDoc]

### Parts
C158  Slot: U6  Rack: SUS-C3  DCC: D1001726  (hidden comment: BI D1001726 Monitors_8xDB9)  (masked out: inside a compile mask, not in the netlist)
C159  DAC0  IOC Card #: 2  Rack: SUS-C3  Slot: U19
C160  DCC: D0902783  Rack: SUS-C4  Slot: U11  (hidden comment: AA D0902783 8xD9)
C161  ADC0  Rack: SUS-C3  Slot: U18  IOC Card #: 1
C162  Rack: SUS-C4  Slot: U10  DCC: D1000305  (hidden comment: AI D1000305 4xD9 18_20_Bit)
C163  DAC1  IOC Card #: 3  Rack: SUS-C3  Slot: U19
C164  Slot: U19  Rack: SUS-C3  IOC Card#: BIO-1  (hidden comment: BIO Contec Card 64Ix64O)  (masked out: inside a compile mask, not in the netlist)
C165  Slot: U7  Rack: SUS-C3  DCC: D1002593  (hidden comment: BO D1002593 Commands_8xDB9)  (masked out: inside a compile mask, not in the netlist)
C166  DAC2  IOC Card #: 4  Rack: SUS-C3  Slot: U19
C167  16-Bit AI Chassis 4X DB9  DCC: D1101521  Rack: SUS-C4  Slot: U2
C190  DCC: D0902783  Rack: SUS-C3  Slot: U7  (hidden comment: AA D0902783 8xD9)
C191  ADC1  Rack: SUS-C3  Slot: U18  IOC Card #: 6
C192  DAC3  IOC Card #: 5  Rack: SUS-C3  Slot: U19
C193  16-Bit AI Chassis 4X DB9  DCC: D1101521  Rack: SUS-C3  Slot: U2

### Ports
IM1 ULLLURLR  BIO IN (see IM1_IM2_IM3_IM4_OSEMs[4A]), IM1 ULLLURLR  BIO OUT (see IM1_IM2_IM3_IM4_OSEMs[4A]), IM1 ULLLURLR  Coil Drive (see IM1_IM2_IM3_IM4_OSEMs[5A]), IM1 ULLLURLR  OSEM PDs (see IM1_IM2_IM3_IM4_OSEMs[5A]), IM2 ULLLURLR  BIO IN (see IM1_IM2_IM3_IM4_OSEMs[4B]), IM2 ULLLURLR  BIO OUT (see IM1_IM2_IM3_IM4_OSEMs[4B]), IM2 ULLLURLR  Coil Drive (see IM1_IM2_IM3_IM4_OSEMs[5B]), IM2 ULLLURLR  OSEM PDs (see IM1_IM2_IM3_IM4_OSEMs[5B]), IM3 ULLLURLR  BIO IN (see IM1_IM2_IM3_IM4_OSEMs[4C]), IM3 ULLLURLR  BIO OUT (see IM1_IM2_IM3_IM4_OSEMs[4C]), IM3 ULLLURLR  Coil Drive (see IM1_IM2_IM3_IM4_OSEMs[5C]), IM3 ULLLURLR  OSEM PDs (see IM1_IM2_IM3_IM4_OSEMs[5C]), IM4 ULLLURLR  BIO IN (see IM1_IM2_IM3_IM4_OSEMs[4D]), IM4 ULLLURLR  BIO OUT (see IM1_IM2_IM3_IM4_OSEMs[4D]), IM4 ULLLURLR  Coil Drive (see IM1_IM2_IM3_IM4_OSEMs[5D]), IM4 ULLLURLR  OSEM PDs (see IM1_IM2_IM3_IM4_OSEMs[5C]), JM1 ULLLURLR  Coil Drive (see JMX_PM1[5A]), JM1 ULLLURLR  OSEM PDs (see JMX_PM1[5B]), JM1 ULLLURLR  VMON (see JMX_PM1[5A]), JM2 ULLLURLR  Coil Drive (see JMX_PM1[5B]), JM2 ULLLURLR  OSEM PDs (see JMX_PM1[5B]), JM2 ULLLURLR  VMON (see JMX_PM1[5B]), JM3 ULLLURLR  Coil Drive (see JMX_PM1[5C]), JM3 ULLLURLR  OSEM PDs (see JMX_PM1[5C]), JM3 ULLLURLR  VMON (see JMX_PM1[5C]), PM1 ULLLURLR  Coil Drive (see JMX_PM1[5D]), PM1 ULLLURLR  OSEM PDs (see JMX_PM1[5C]), RM1 ULLLURLR  Coil Drive (see RM1_RM2[5A]), RM1 ULLLURLR  OSEM PDs (see RM1_RM2[5B]), RM2 ULLLURLR  Coil Drive (see RM1_RM2[5B]), RM2 ULLLURLR  OSEM PDs (see RM1_RM2[5B])

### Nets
HAM1_ISC_332: C192.SCSI(Output) C193.SCSI(To_DAC)
HAM1_ISC_333: C190.SCSI(ToADC) C191.SCSI(Output)
ISC_288: C166.SCSI(Output) C167.SCSI(To_DAC)
ISC_HAM1_125: C160.D9M(IN17-20) ; port RM1 ULLLURLR  OSEM PDs
ISC_HAM1_126: C160.D9M(IN21-24) ; port RM2 ULLLURLR  OSEM PDs
ISC_HAM1_192: C167.D9F(OUT0-3) ; port RM1 ULLLURLR  Coil Drive
ISC_HAM1_193: C167.D9F(OUT4-7) ; port RM2 ULLLURLR  Coil Drive
ISC_HAM1_316: C190.D9M(IN1-4) ; port JM1 ULLLURLR  OSEM PDs
ISC_HAM1_317: C190.D9M(IN5-8) ; port JM2 ULLLURLR  OSEM PDs
ISC_HAM1_318: C190.D9M(IN9-12) ; port JM3 ULLLURLR  OSEM PDs
ISC_HAM1_319: C160.D9M(IN25-28) ; port PM1 ULLLURLR  OSEM PDs
ISC_HAM1_320: C190.D9M(IN13-16) ; port JM1 ULLLURLR  VMON
ISC_HAM1_321: C190.D9M(IN17-20) ; port JM2 ULLLURLR  VMON
ISC_HAM1_322: C190.D9M(IN21-24) ; port JM3 ULLLURLR  VMON
ISC_HAM1_324: C193.D9F(OUT0-3) ; port JM1 ULLLURLR  Coil Drive
ISC_HAM1_325: C193.D9F(OUT4-7) ; port JM2 ULLLURLR  Coil Drive
ISC_HAM1_326: C193.D9F(OUT8-11) ; port JM3 ULLLURLR  Coil Drive
ISC_HAM1_327: C167.D9F(OUT8-11) ; port PM1 ULLLURLR  Coil Drive
SUS_HAM2_161: C160.D9M(IN1-4) ; port IM1 ULLLURLR  OSEM PDs
SUS_HAM2_163: C160.D9M(IN5-8) ; port IM4 ULLLURLR  OSEM PDs
SUS_HAM2_166: C162.D9F(OUT1-4) ; port IM1 ULLLURLR  Coil Drive
SUS_HAM2_167: C162.D9F(OUT5-8) ; port IM4 ULLLURLR  Coil Drive
SUS_HAM2_174: C160.D9M(IN9-12) ; port IM2 ULLLURLR  OSEM PDs
SUS_HAM2_176: C160.D9M(IN13-16) ; port IM3 ULLLURLR  OSEM PDs
SUS_HAM2_179: C162.D9F(OUT9-12) ; port IM2 ULLLURLR  Coil Drive
SUS_HAM2_180: C162.D9F(OUT13-16) ; port IM3 ULLLURLR  Coil Drive
SUS_HAM2_187: C160.SCSI(ToADC) C161.SCSI(Output)
SUS_HAM2_189: C159.DB25F(Output) C162.D25M(To_DAC_0)
SUS_HAM2_190: C162.D25M(To_DAC_1) C163.DB25F(Output)

Not connected (* = marked no-connect by the designer): C160 Conec-3(DC+/-18)*; C162 Conec-3(DC+/-18)*; C167 Conec-3(+/-18)*; C190 Conec-3(DC+/-18)*; C193 Conec-3(+/-18)*

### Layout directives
Length: 6ft; DCC: HPDB68 M/M: HAM1_ISC_332, HAM1_ISC_333, ISC_288, SUS_HAM2_187
Length: 6ft; DCC: D2100752: SUS_HAM2_189, SUS_HAM2_190
Length: 6ft; DCC: PCB100WS: (no net found under the mark)

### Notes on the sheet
- SPARE
- BIO for IM1-4 to be removed
- DUO TONE CH 31 & 32

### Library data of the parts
C158 = BI D1001726 Monitors_8xDB9: Serial: Sxxxxxxx; System: SUS
C159 C163 = DAC-20: 8 Chan, 20 Bit DAC
C160 C190 = AA D0902783 8xD9: Serial: Sxxxxxxx; System: SUS
C161 C191 = ADC-16: 16 Chan, 16 Bit ADC
C162 = AI D1000305 4xD9 18_20_Bit: System: SUS; Serial: Sxxxxxxx
C164 = BIO Contec Card 64Ix64O: System: SUS
C165 = BO D1002593 Commands_8xDB9: Serial: Sxxxxxxx; System: SUS
C166 C192 = DAC-16: 16 Chan, 16 Bit DAC
C167 C193 = AI_9pin_16_bit: AI Chassis 4X DB9 16-bit; Serial: Sxxxxxxx; System: ISC

## Sheet SUSAUXH2_ADC_Monitors.SchDoc: SUSAUXH2_ADC_DAC_BIO
size C; Organization: LIGO Laboratory; Address1: California Institute of Technology; Address2: Massachusetts Institute of Technology; DocumentNumber: D0902810; Revision: v11; SheetNumber: 12; SheetTotal: 14; Engineer: J.Kissel/L.Sánchez
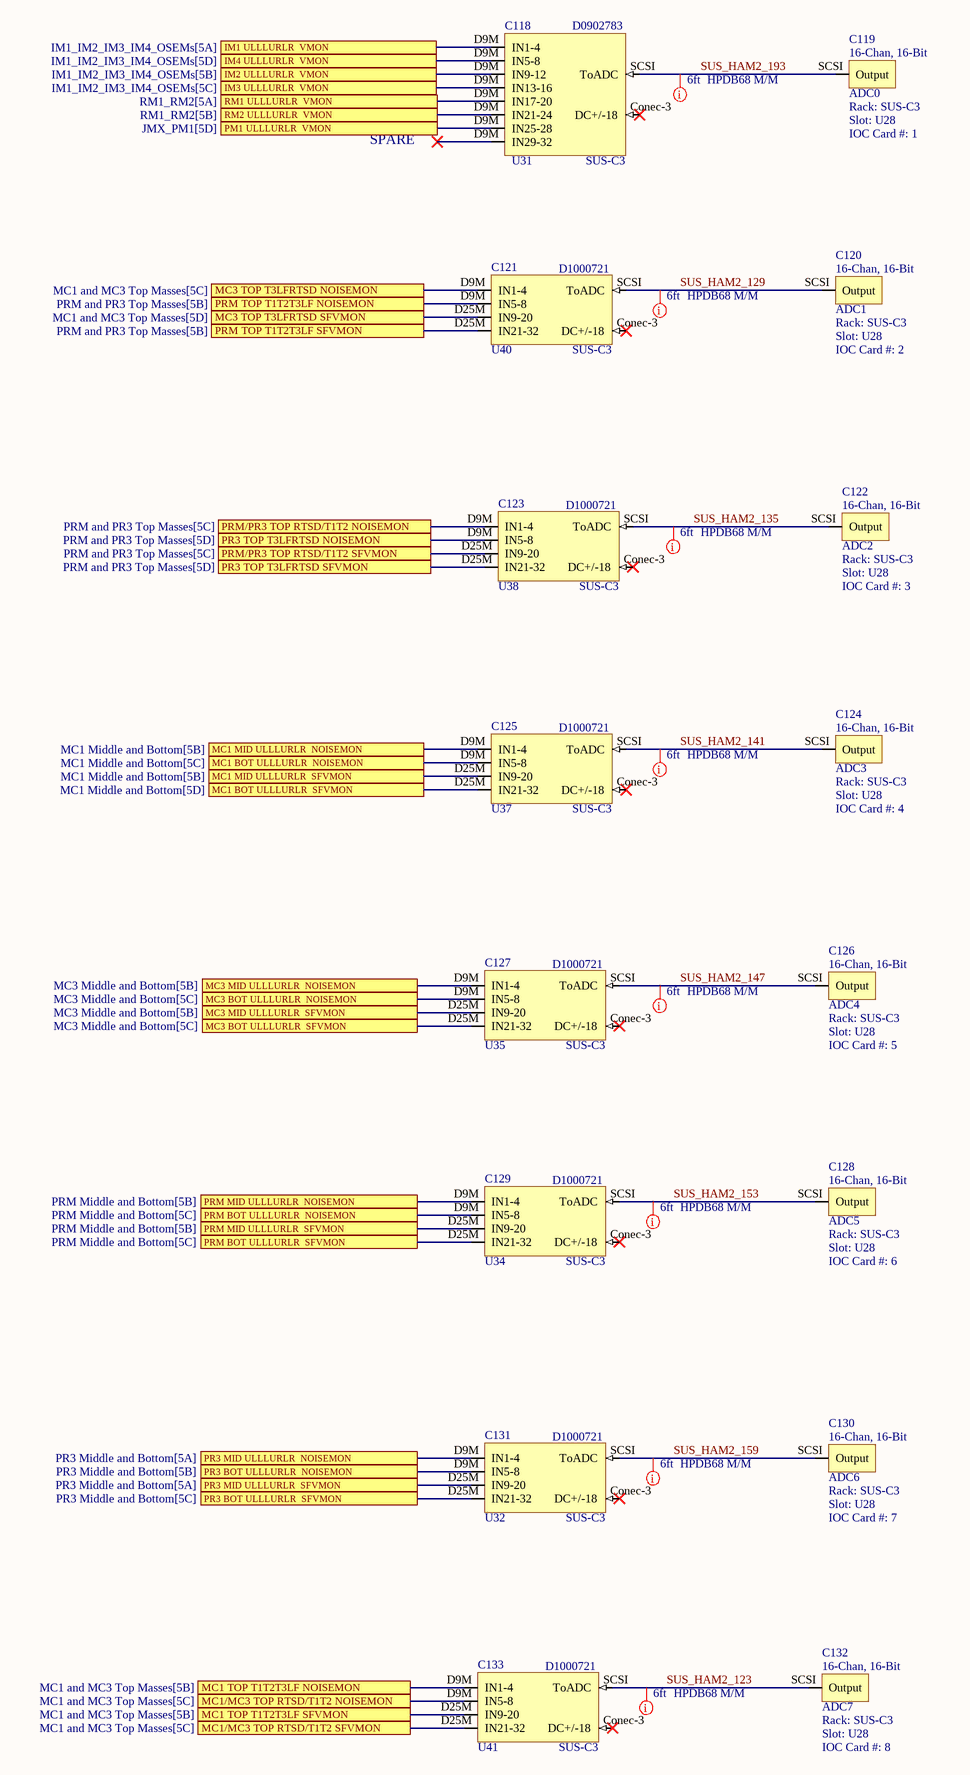
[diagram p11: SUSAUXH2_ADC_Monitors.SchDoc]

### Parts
C118  DCC: D0902783  Rack: SUS-C3  Slot: U31  (hidden comment: AA D0902783 8xD9)
C119  ADC0  Rack: SUS-C3  Slot: U28  IOC Card #: 1
C120  ADC1  Rack: SUS-C3  Slot: U28  IOC Card #: 2
C121  Slot: U40  Rack: SUS-C3  DCC: D1000721  (hidden comment: AA D1000721 2xD9 2xD25)
C122  ADC2  Rack: SUS-C3  Slot: U28  IOC Card #: 3
C123  Slot: U38  Rack: SUS-C3  DCC: D1000721  (hidden comment: AA D1000721 2xD9 2xD25)
C124  ADC3  Rack: SUS-C3  Slot: U28  IOC Card #: 4
C125  Slot: U37  Rack: SUS-C3  DCC: D1000721  (hidden comment: AA D1000721 2xD9 2xD25)
C126  ADC4  Rack: SUS-C3  Slot: U28  IOC Card #: 5
C127  Slot: U35  Rack: SUS-C3  DCC: D1000721  (hidden comment: AA D1000721 2xD9 2xD25)
C128  ADC5  Rack: SUS-C3  Slot: U28  IOC Card #: 6
C129  Slot: U34  Rack: SUS-C3  DCC: D1000721  (hidden comment: AA D1000721 2xD9 2xD25)
C130  ADC6  Rack: SUS-C3  Slot: U28  IOC Card #: 7
C131  Slot: U32  Rack: SUS-C3  DCC: D1000721  (hidden comment: AA D1000721 2xD9 2xD25)
C132  ADC7  Rack: SUS-C3  Slot: U28  IOC Card #: 8
C133  Slot: U41  Rack: SUS-C3  DCC: D1000721  (hidden comment: AA D1000721 2xD9 2xD25)

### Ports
IM1 ULLLURLR  VMON (see IM1_IM2_IM3_IM4_OSEMs[5A]), IM2 ULLLURLR  VMON (see IM1_IM2_IM3_IM4_OSEMs[5B]), IM3 ULLLURLR  VMON (see IM1_IM2_IM3_IM4_OSEMs[5C]), IM4 ULLLURLR  VMON (see IM1_IM2_IM3_IM4_OSEMs[5D]), MC1 BOT ULLLURLR  NOISEMON (see MC1 Middle and Bottom[5C]), MC1 BOT ULLLURLR  SFVMON (see MC1 Middle and Bottom[5D]), MC1 MID ULLLURLR  NOISEMON (see MC1 Middle and Bottom[5B]), MC1 MID ULLLURLR  SFVMON (see MC1 Middle and Bottom[5B]), MC1 TOP T1T2T3LF NOISEMON (see MC1 and MC3 Top Masses[5B]), MC1 TOP T1T2T3LF SFVMON (see MC1 and MC3 Top Masses[5B]), MC1/MC3 TOP RTSD/T1T2 NOISEMON (see MC1 and MC3 Top Masses[5C]), MC1/MC3 TOP RTSD/T1T2 SFVMON (see MC1 and MC3 Top Masses[5C]), MC3 BOT ULLLURLR  NOISEMON (see MC3 Middle and Bottom[5C]), MC3 BOT ULLLURLR  SFVMON (see MC3 Middle and Bottom[5C]), MC3 MID ULLLURLR  NOISEMON (see MC3 Middle and Bottom[5B]), MC3 MID ULLLURLR  SFVMON (see MC3 Middle and Bottom[5B]), MC3 TOP T3LFRTSD NOISEMON (see MC1 and MC3 Top Masses[5C]), MC3 TOP T3LFRTSD SFVMON (see MC1 and MC3 Top Masses[5D]), PM1 ULLLURLR  VMON (see JMX_PM1[5D]), PR3 BOT ULLLURLR  NOISEMON (see PR3 Middle and Bottom[5B]), PR3 BOT ULLLURLR  SFVMON (see PR3 Middle and Bottom[5C]), PR3 MID ULLLURLR  NOISEMON (see PR3 Middle and Bottom[5A]), PR3 MID ULLLURLR  SFVMON (see PR3 Middle and Bottom[5A]), PR3 TOP T3LFRTSD NOISEMON (see PRM and PR3 Top Masses[5D]), PR3 TOP T3LFRTSD SFVMON (see PRM and PR3 Top Masses[5D]), PRM BOT ULLLURLR  NOISEMON (see PRM Middle and Bottom[5C]), PRM BOT ULLLURLR  SFVMON (see PRM Middle and Bottom[5C]), PRM MID ULLLURLR  NOISEMON (see PRM Middle and Bottom[5B]), PRM MID ULLLURLR  SFVMON (see PRM Middle and Bottom[5B]), PRM TOP T1T2T3LF NOISEMON (see PRM and PR3 Top Masses[5B]), PRM TOP T1T2T3LF SFVMON (see PRM and PR3 Top Masses[5B]), PRM/PR3 TOP RTSD/T1T2 NOISEMON (see PRM and PR3 Top Masses[5C]), PRM/PR3 TOP RTSD/T1T2 SFVMON (see PRM and PR3 Top Masses[5C]), RM1 ULLLURLR  VMON (see RM1_RM2[5A]), RM2 ULLLURLR  VMON (see RM1_RM2[5B])

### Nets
ISC_HAM1_184: C118.D9M(IN17-20) ; port RM1 ULLLURLR  VMON
ISC_HAM1_185: C118.D9M(IN21-24) ; port RM2 ULLLURLR  VMON
ISC_HAM1_323: C118.D9M(IN25-28) ; port PM1 ULLLURLR  VMON
SUS_HAM2_119: C133.D9M(IN1-4) ; port MC1 TOP T1T2T3LF NOISEMON
SUS_HAM2_120: C133.D9M(IN5-8) ; port MC1/MC3 TOP RTSD/T1T2 NOISEMON
SUS_HAM2_121: C133.D25M(IN9-20) ; port MC1 TOP T1T2T3LF SFVMON
SUS_HAM2_122: C133.D25M(IN21-32) ; port MC1/MC3 TOP RTSD/T1T2 SFVMON
SUS_HAM2_123: C132.SCSI(Output) C133.SCSI(ToADC)
SUS_HAM2_125: C121.D9M(IN1-4) ; port MC3 TOP T3LFRTSD NOISEMON
SUS_HAM2_126: C121.D9M(IN5-8) ; port PRM TOP T1T2T3LF NOISEMON
SUS_HAM2_127: C121.D25M(IN9-20) ; port MC3 TOP T3LFRTSD SFVMON
SUS_HAM2_128: C121.D25M(IN21-32) ; port PRM TOP T1T2T3LF SFVMON
SUS_HAM2_129: C120.SCSI(Output) C121.SCSI(ToADC)
SUS_HAM2_131: C123.D9M(IN1-4) ; port PRM/PR3 TOP RTSD/T1T2 NOISEMON
SUS_HAM2_132: C123.D9M(IN5-8) ; port PR3 TOP T3LFRTSD NOISEMON
SUS_HAM2_133: C123.D25M(IN9-20) ; port PRM/PR3 TOP RTSD/T1T2 SFVMON
SUS_HAM2_134: C123.D25M(IN21-32) ; port PR3 TOP T3LFRTSD SFVMON
SUS_HAM2_135: C122.SCSI(Output) C123.SCSI(ToADC)
SUS_HAM2_137: C125.D9M(IN1-4) ; port MC1 MID ULLLURLR  NOISEMON
SUS_HAM2_138: C125.D9M(IN5-8) ; port MC1 BOT ULLLURLR  NOISEMON
SUS_HAM2_139: C125.D25M(IN9-20) ; port MC1 MID ULLLURLR  SFVMON
SUS_HAM2_140: C125.D25M(IN21-32) ; port MC1 BOT ULLLURLR  SFVMON
SUS_HAM2_141: C124.SCSI(Output) C125.SCSI(ToADC)
SUS_HAM2_143: C127.D9M(IN1-4) ; port MC3 MID ULLLURLR  NOISEMON
SUS_HAM2_144: C127.D9M(IN5-8) ; port MC3 BOT ULLLURLR  NOISEMON
SUS_HAM2_145: C127.D25M(IN9-20) ; port MC3 MID ULLLURLR  SFVMON
SUS_HAM2_146: C127.D25M(IN21-32) ; port MC3 BOT ULLLURLR  SFVMON
SUS_HAM2_147: C126.SCSI(Output) C127.SCSI(ToADC)
SUS_HAM2_149: C129.D9M(IN1-4) ; port PRM MID ULLLURLR  NOISEMON
SUS_HAM2_150: C129.D9M(IN5-8) ; port PRM BOT ULLLURLR  NOISEMON
SUS_HAM2_151: C129.D25M(IN9-20) ; port PRM MID ULLLURLR  SFVMON
SUS_HAM2_152: C129.D25M(IN21-32) ; port PRM BOT ULLLURLR  SFVMON
SUS_HAM2_153: C128.SCSI(Output) C129.SCSI(ToADC)
SUS_HAM2_155: C131.D9M(IN1-4) ; port PR3 MID ULLLURLR  NOISEMON
SUS_HAM2_156: C131.D9M(IN5-8) ; port PR3 BOT ULLLURLR  NOISEMON
SUS_HAM2_157: C131.D25M(IN9-20) ; port PR3 MID ULLLURLR  SFVMON
SUS_HAM2_158: C131.D25M(IN21-32) ; port PR3 BOT ULLLURLR  SFVMON
SUS_HAM2_159: C130.SCSI(Output) C131.SCSI(ToADC)
SUS_HAM2_193: C118.SCSI(ToADC) C119.SCSI(Output)
SUS_HAM2_235: C118.D9M(IN1-4) ; port IM1 ULLLURLR  VMON
SUS_HAM2_236: C118.D9M(IN5-8) ; port IM4 ULLLURLR  VMON
SUS_HAM2_237: C118.D9M(IN9-12) ; port IM2 ULLLURLR  VMON
SUS_HAM2_238: C118.D9M(IN13-16) ; port IM3 ULLLURLR  VMON

Not connected (* = marked no-connect by the designer): C118 Conec-3(DC+/-18)*; C121 Conec-3(DC+/-18)*; C123 Conec-3(DC+/-18)*; C125 Conec-3(DC+/-18)*; C127 Conec-3(DC+/-18)*; C129 Conec-3(DC+/-18)*; C131 Conec-3(DC+/-18)*; C133 Conec-3(DC+/-18)*

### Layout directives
Length: 6ft; DCC: HPDB68 M/M: SUS_HAM2_123, SUS_HAM2_129, SUS_HAM2_135, SUS_HAM2_141, SUS_HAM2_147, SUS_HAM2_153, SUS_HAM2_159, SUS_HAM2_193

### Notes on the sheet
- SPARE

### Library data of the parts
C118 = AA D0902783 8xD9: Serial: Sxxxxxxx; System: SUS
C119 C120 C122 C124 C126 C128 C130 C132 = ADC-16: 16 Chan, 16 Bit ADC
C121 C123 C125 C127 C129 C131 C133 = AA D1000721 2xD9 2xD25: Serial: Sxxxxxxx; System: SUS; Parameter: AA chassis

## Sheet RACK_SUS_R1_R2.SchDoc: R1 & R2 Rack
size C; Organization: LIGO Laboratory; Address1: California Institute of Technology; Address2: Massachusetts Institute of Technology; DocumentNumber: D0902810; Revision: v11; SheetNumber: 13; SheetTotal: 14; Engineer: J.Kissel/L.Sánchez
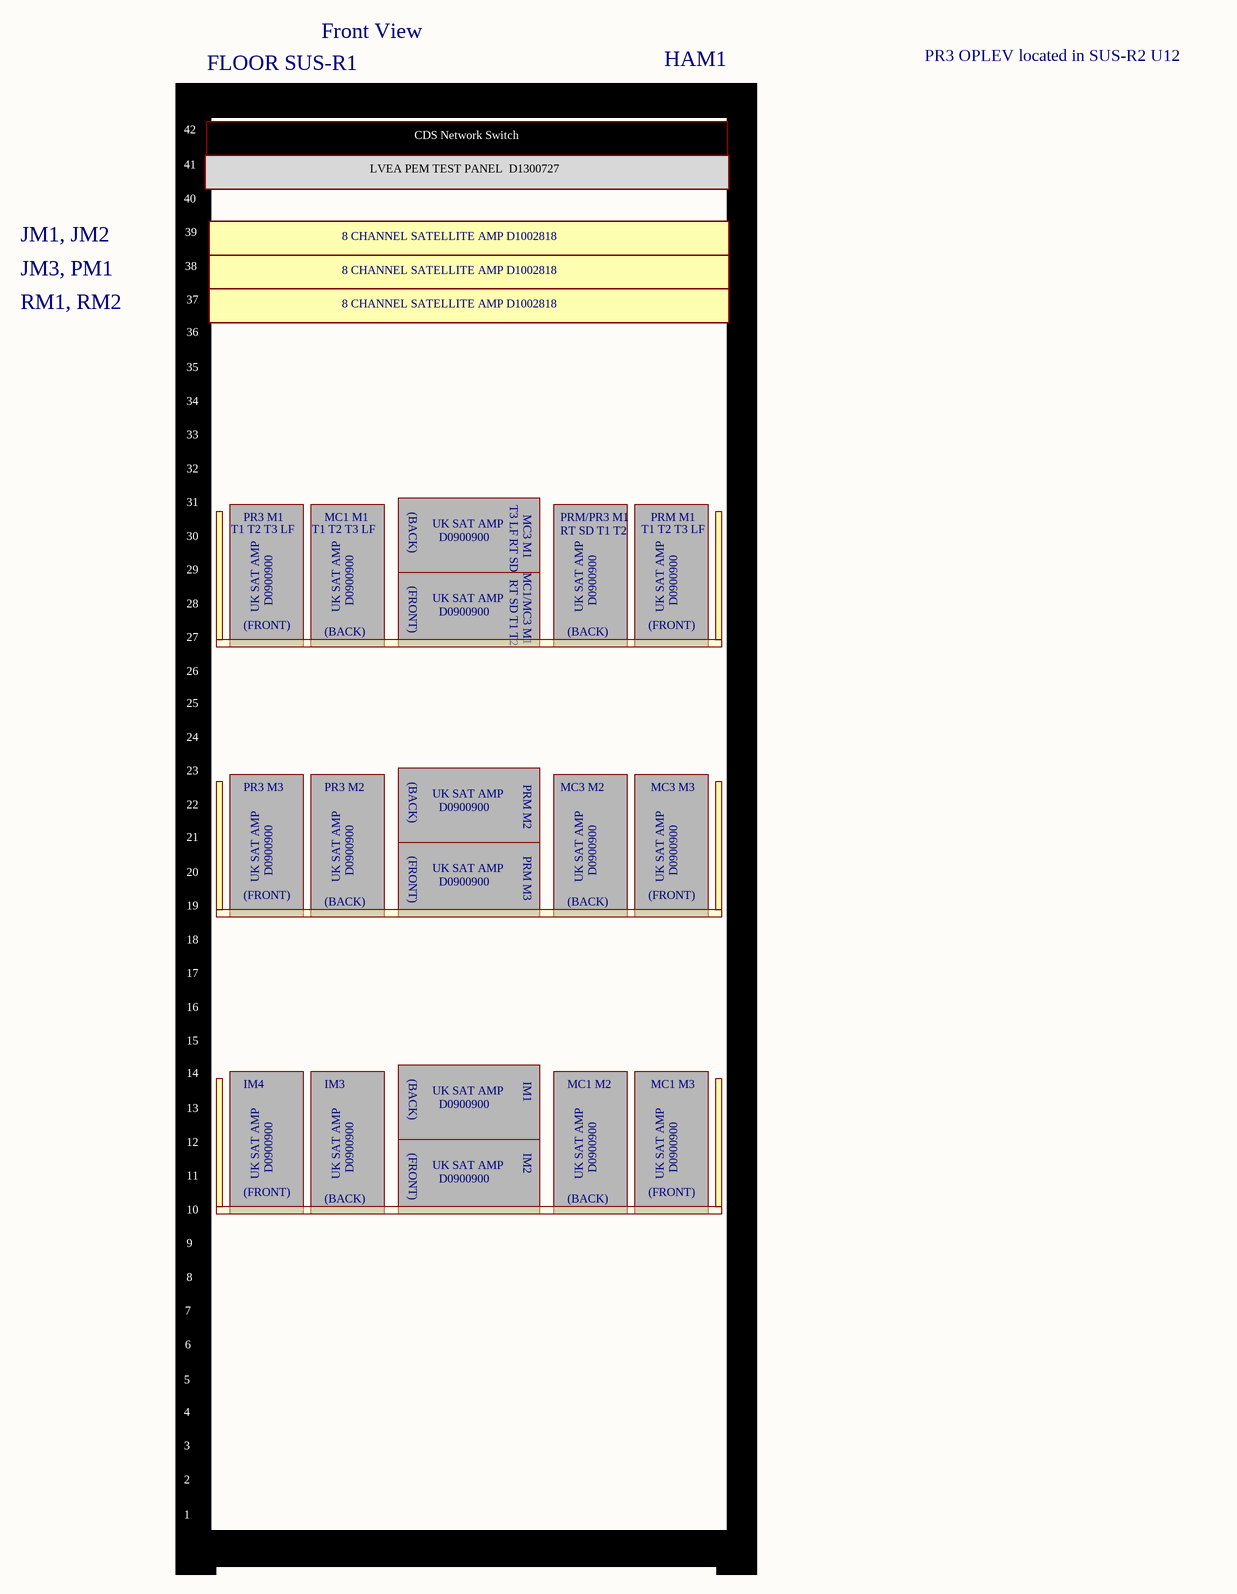
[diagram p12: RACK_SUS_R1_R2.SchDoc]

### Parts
RackR1  1U  Rack 42 pos  (value not drawn)  (part B of 2)

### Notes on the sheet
- FLOOR SUS-R1
- Front View
- HAM1
- PR3 OPLEV located in SUS-R2 U12
- CDS Network Switch
- LVEA PEM TEST PANEL  D1300727
- JM1, JM2
- JM3, PM1
- 8 CHANNEL SATELLITE AMP D1002818
- RM1, RM2
- T3 LF RT SD
- T1 T2 T3 LF
- PR3 M1
- MC1 M1
- (BACK)
- UK SAT AMP
- D0900900
- MC3 M1
- PRM/PR3 M1
- RT SD T1 T2
- PRM M1
- (FRONT)
- MC1/MC3 M1
- PR3 M3
- PR3 M2
- (near RackR1) (BACK)
- (near RackR1) UK SAT AMP
- (near RackR1) D0900900
- PRM M2
- MC3 M2
- MC3 M3
- PRM M3
- IM4
- IM3
- IM1
- MC1 M2
- MC1 M3
- IM2

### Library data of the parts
RackR1 = RACK_42

## Sheet RACK_SUS_C3_C4.SchDoc: C3 & C4 Rack
size C; Organization: LIGO Laboratory; Address1: California Institute of Technology; Address2: Massachusetts Institute of Technology; DocumentNumber: D0902810; Revision: v11; SheetNumber: 14; SheetTotal: 14; Engineer: J.Kissel/L.Sánchez
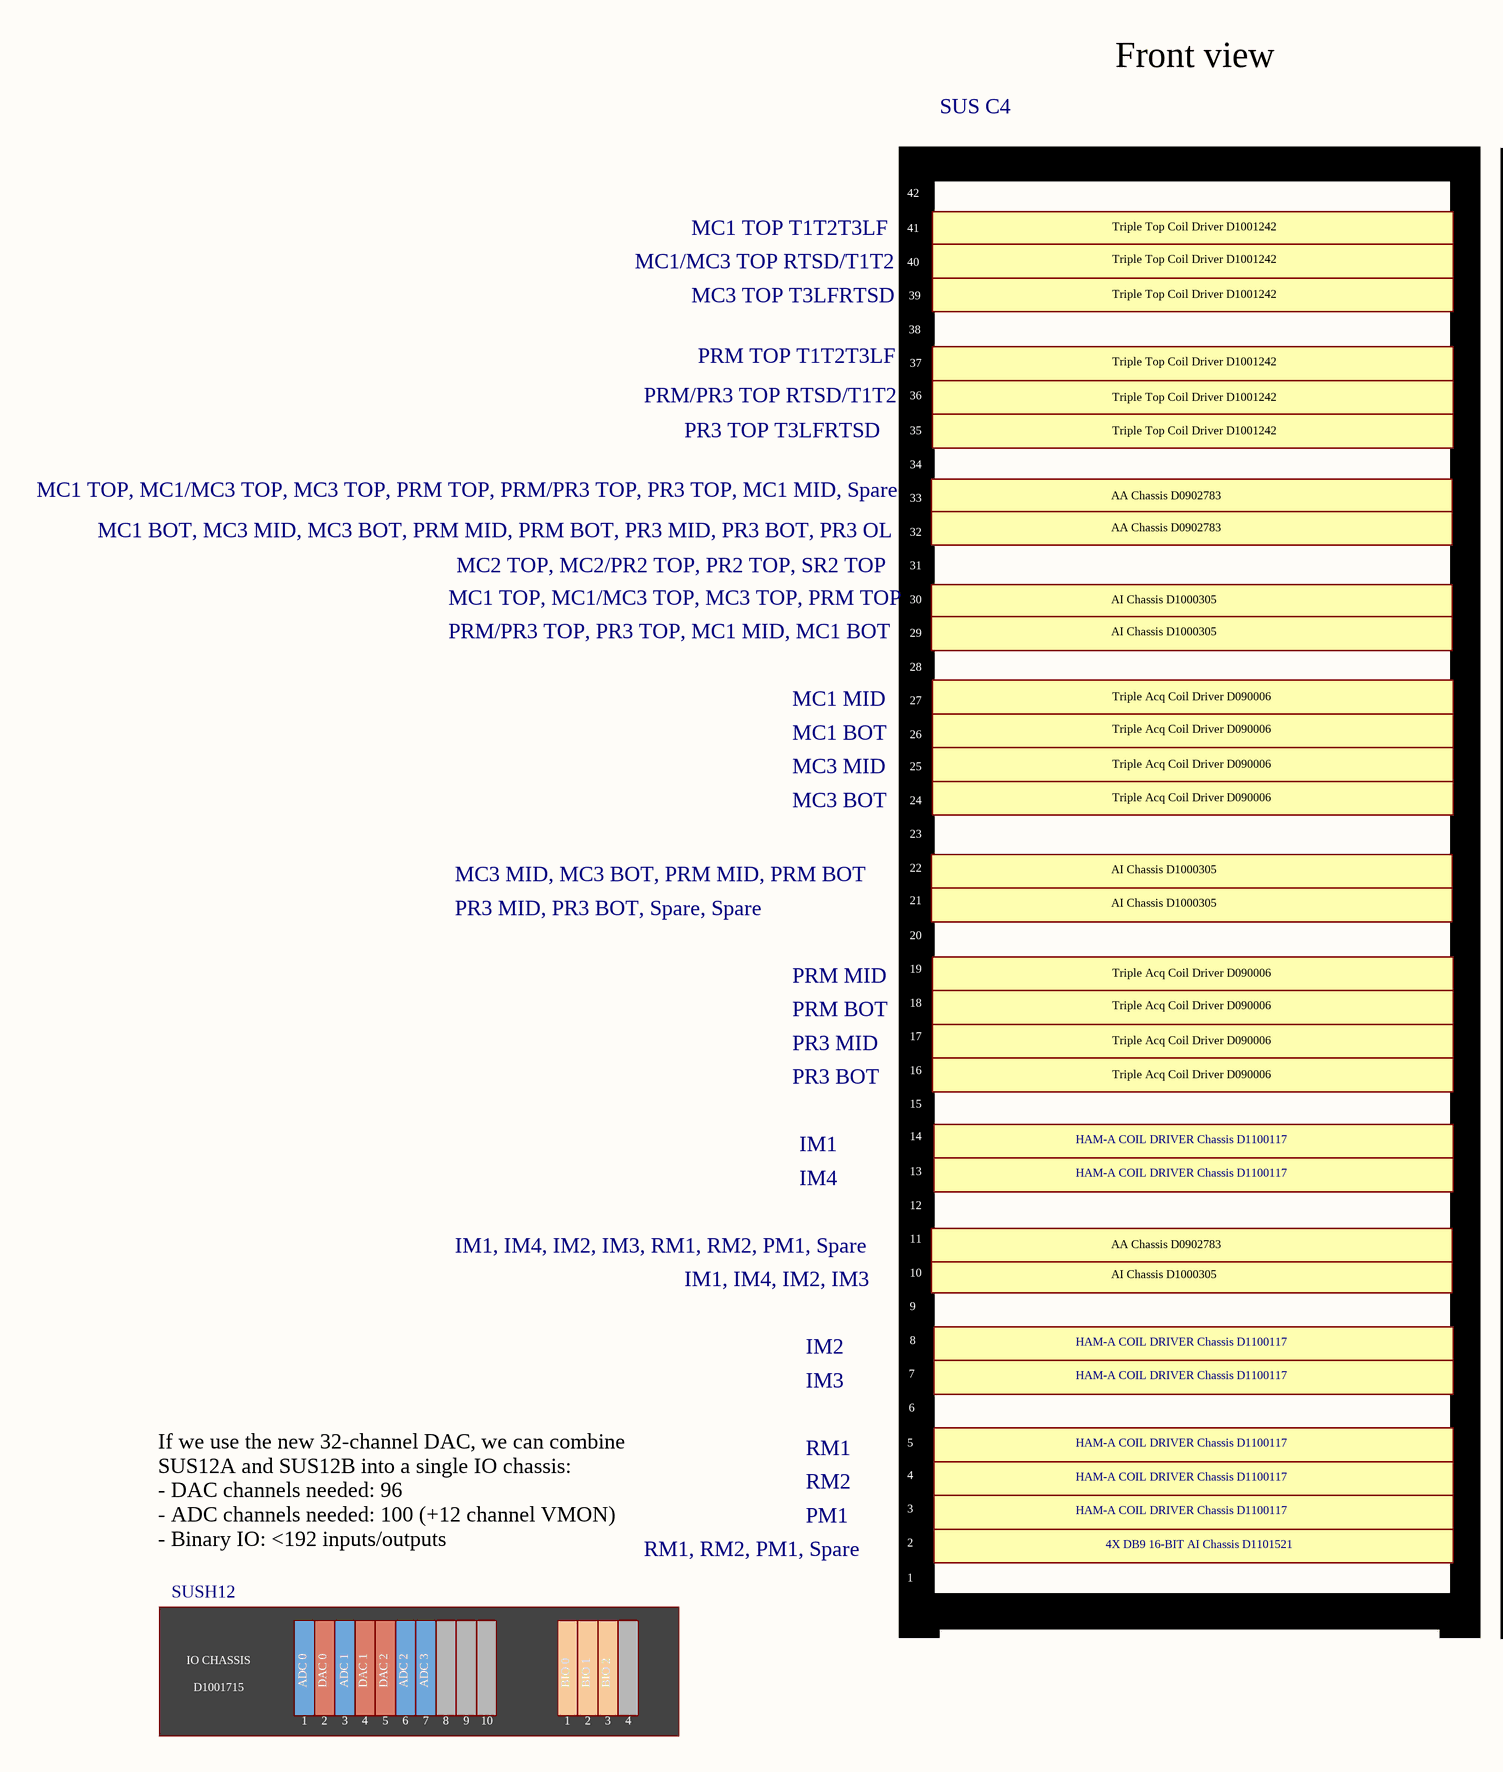
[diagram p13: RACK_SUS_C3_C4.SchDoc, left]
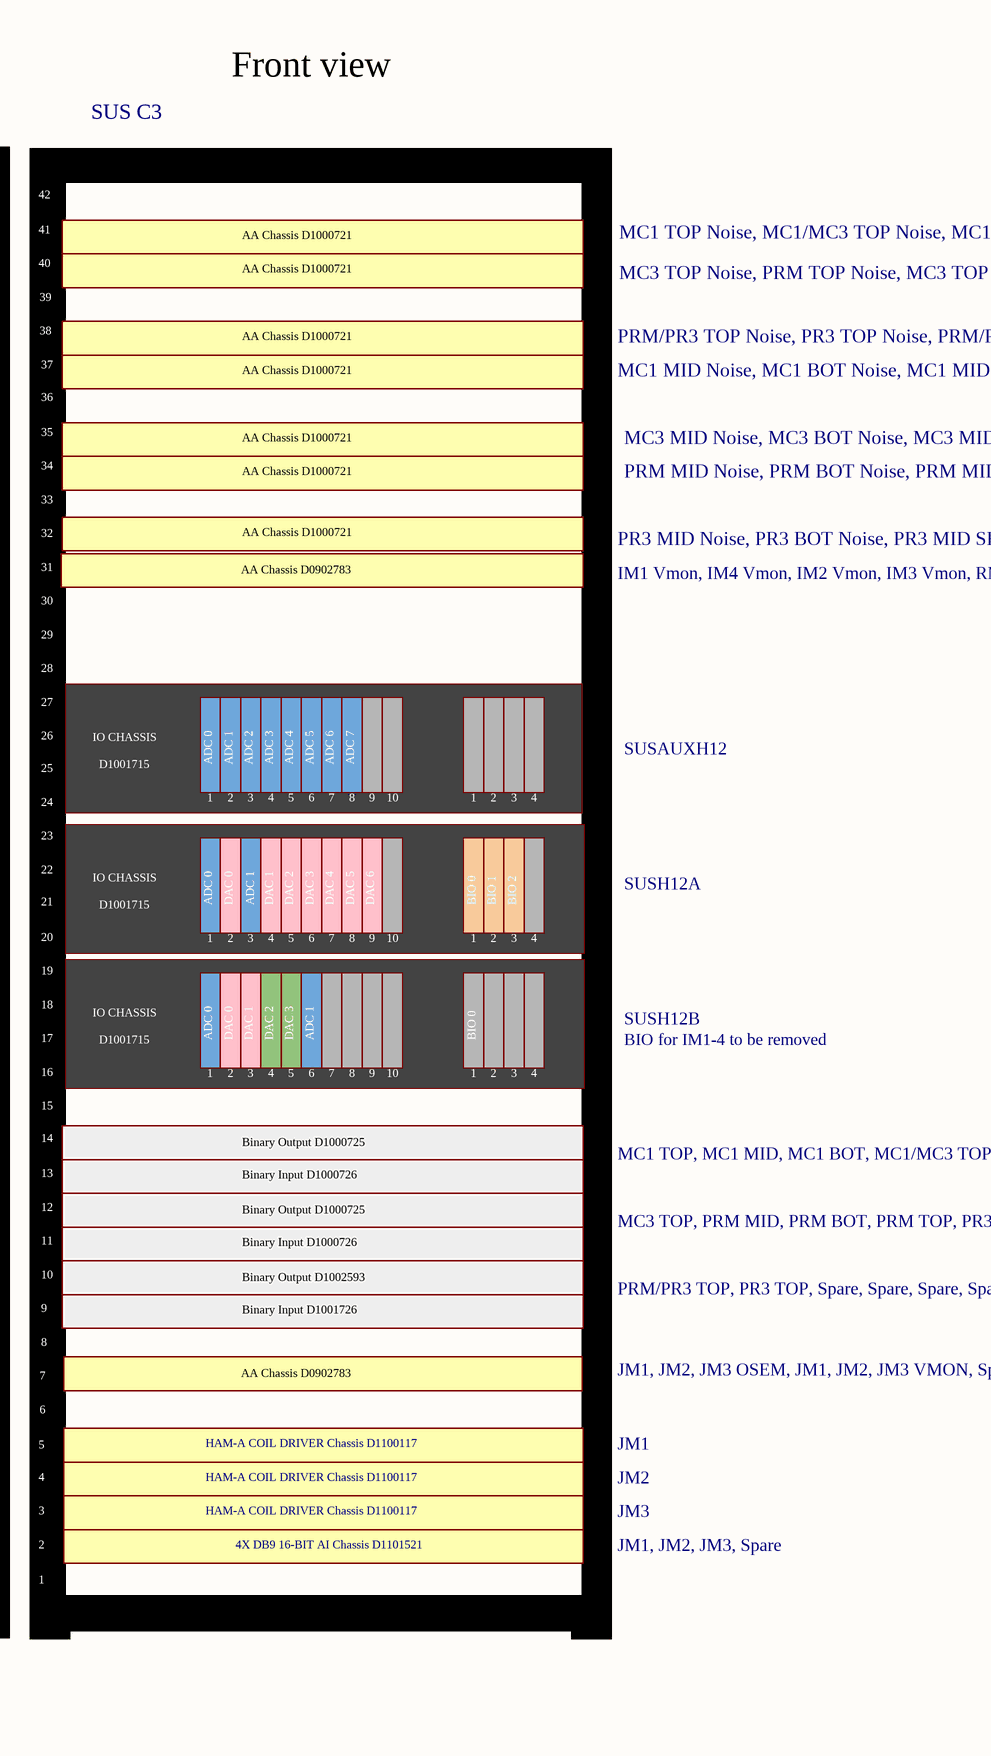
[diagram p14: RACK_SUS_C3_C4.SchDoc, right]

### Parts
Rack1  1U  Rack 42 pos  (value not drawn)  (parts A,B of 2)

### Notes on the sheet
- Front view
- SUS C4
- SUS C3
- MC1/MC3 TOP RTSD/T1T2
- MC1 TOP T1T2T3LF
- Triple Top Coil Driver D1001242
- AA Chassis D1000721
- MC1 TOP Noise, MC1/MC3 TOP Noise, MC1 TOP SFV, MC1/MC3 TOP SFV
- MC3 TOP Noise, PRM TOP Noise, MC3 TOP SFV, PRM TOP SFV
- MC3 TOP T3LFRTSD
- PRM/PR3 TOP Noise, PR3 TOP Noise, PRM/PR3 TOP SFV, PR3 TOP SFV
- PRM/PR3 TOP RTSD/T1T2
- PRM TOP T1T2T3LF
- MC1 MID Noise, MC1 BOT Noise, MC1 MID SFV, MC1 BOT SFV
- PR3 TOP T3LFRTSD
- MC3 MID Noise, MC3 BOT Noise, MC3 MID SFV, MC3 BOT SFV
- PRM MID Noise, PRM BOT Noise, PRM MID SFV, PRM BOT SFV
- MC1 TOP, MC1/MC3 TOP, MC3 TOP, PRM TOP, PRM/PR3 TOP, PR3 TOP, MC1 MID, Spare
- MC1 BOT, MC3 MID, MC3 BOT, PRM MID, PRM BOT, PR3 MID, PR3 BOT, PR3 OL
- AA Chassis D0902783
- PR3 MID Noise, PR3 BOT Noise, PR3 MID SFV, PR3 BOT SFV
- MC1 TOP, MC1/MC3 TOP, MC3 TOP, PRM TOP
- MC2 TOP, MC2/PR2 TOP, PR2 TOP, SR2 TOP
- AI Chassis D1000305
- IM1 Vmon, IM4 Vmon, IM2 Vmon, IM3 Vmon, RM1, RM2 Vmon, PM1 VMon, Spare
- PRM/PR3 TOP, PR3 TOP, MC1 MID, MC1 BOT
- MC1 MID
- MC1 BOT
- Triple Acq Coil Driver D090006
- IO CHASSIS
- ADC 0
- ADC 1
- ADC 2
- ADC 3
- ADC 4
- ADC 5
- ADC 6
- ADC 7
- SUSAUXH12
- MC3 MID
- MC3 BOT
- D1001715
- 1
- 2
- 3
- 4
- 5
- 6
- 7
- 8
- 9
- 10
- MC3 MID, MC3 BOT, PRM MID, PRM BOT
- SUSH12A
- PR3 MID, PR3 BOT, Spare, Spare
- (near Rack1) AI Chassis D1000305
- DAC 0
- (near Rack1) DAC 1
- (near Rack1) 5
- (near Rack1) DAC 2
- (near Rack1) 6
- (near Rack1) DAC 3
- (near Rack1) 7
- (near Rack1) DAC 4
- (near Rack1) 8
- (near Rack1) DAC 5
- (near Rack1) DAC 6
- BIO 0
- BIO 1
- BIO 2
- PRM MID
- PRM BOT
- (near Rack1) Triple Acq Coil Driver D090006
- SUSH12B
- PR3 MID
- PR3 BOT
- DAC 1
- DAC 2
- DAC 3
- BIO for IM1-4 to be removed
- IM1
- HAM-A COIL DRIVER Chassis D1100117
- Binary Output D1000725
- MC1 TOP, MC1 MID, MC1 BOT, MC1/MC3 TOP, MC3 MID, MC3 BOT
- IM4
- Binary Input D1000726
- MC3 TOP, PRM MID, PRM BOT, PRM TOP, PR3 MID, PR3 BOT
- IM1, IM4, IM2, IM3, RM1, RM2, PM1, Spare
- IM1, IM4, IM2, IM3
- Binary Output D1002593
- PRM/PR3 TOP, PR3 TOP, Spare, Spare, Spare, Spare, Spare, Spare
- IM2
- Binary Input D1001726
- IM3
- JM1, JM2, JM3 OSEM, JM1, JM2, JM3 VMON, Spare, Spare
- RM1
- RM2
- JM1
- JM2
- If we use the new 32-channel DAC, we can combine SUS12A and SUS12B into a single IO chassis:
  - DAC channels needed: 96
  - ADC channels needed: 100 (+12 channel VMON)
  - Binary IO: <192 inputs/outputs
- RM1, RM2, PM1, Spare
- PM1
- 4X DB9 16-BIT AI Chassis D1101521
- JM3
- JM1, JM2, JM3, Spare
- SUSH12

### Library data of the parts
Rack1 = RACK_42

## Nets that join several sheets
ISC_HAM1_125: RM1_RM2 (C112.D9F), SUSH2B_ADC_DAC_BIO (C160.D9M)
ISC_HAM1_126: RM1_RM2 (C112.D9F), SUSH2B_ADC_DAC_BIO (C160.D9M)
ISC_HAM1_184: RM1_RM2 (C107.D9F), SUSAUXH2_ADC_Monitors (C118.D9M)
ISC_HAM1_185: RM1_RM2 (C117.D9F), SUSAUXH2_ADC_Monitors (C118.D9M)
ISC_HAM1_192: RM1_RM2 (C107.D9M), SUSH2B_ADC_DAC_BIO (C167.D9F)
ISC_HAM1_193: RM1_RM2 (C117.D9M), SUSH2B_ADC_DAC_BIO (C167.D9F)
ISC_HAM1_316: JMX_PM1 (C173.D9F), SUSH2B_ADC_DAC_BIO (C190.D9M)
ISC_HAM1_317: JMX_PM1 (C173.D9F), SUSH2B_ADC_DAC_BIO (C190.D9M)
ISC_HAM1_318: JMX_PM1 (C184.D9F), SUSH2B_ADC_DAC_BIO (C190.D9M)
ISC_HAM1_319: JMX_PM1 (C184.D9F), SUSH2B_ADC_DAC_BIO (C160.D9M)
ISC_HAM1_320: JMX_PM1 (C168.D9F), SUSH2B_ADC_DAC_BIO (C190.D9M)
ISC_HAM1_321: JMX_PM1 (C178.D9F), SUSH2B_ADC_DAC_BIO (C190.D9M)
ISC_HAM1_322: JMX_PM1 (C179.D9F), SUSH2B_ADC_DAC_BIO (C190.D9M)
ISC_HAM1_323: JMX_PM1 (C185.D9F), SUSAUXH2_ADC_Monitors (C118.D9M)
ISC_HAM1_324: JMX_PM1 (C168.D9M), SUSH2B_ADC_DAC_BIO (C193.D9F)
ISC_HAM1_325: JMX_PM1 (C178.D9M), SUSH2B_ADC_DAC_BIO (C193.D9F)
ISC_HAM1_326: JMX_PM1 (C179.D9M), SUSH2B_ADC_DAC_BIO (C193.D9F)
ISC_HAM1_327: JMX_PM1 (C185.D9M), SUSH2B_ADC_DAC_BIO (C167.D9F)
SUS_ OPLEV_PR3_AA: PR3 Middle and Bottom (C194.D9F), SUSH2A_ADC_DAC_BIO (C142.D9M)
SUS_HAM2_043: MC1 and MC3 Top Masses (C30.D37F), SUSH2A_ADC_DAC_BIO (C135.D9M)
SUS_HAM2_044: MC1 and MC3 Top Masses (C30.D37M), SUSH2A_ADC_DAC_BIO (C141.D9F)
SUS_HAM2_045: MC1 and MC3 Top Masses (C35.D37F), SUSH2A_ADC_DAC_BIO (C135.D9M)
SUS_HAM2_046: MC1 and MC3 Top Masses (C35.D37M), SUSH2A_ADC_DAC_BIO (C141.D9F)
SUS_HAM2_047: MC1 and MC3 Top Masses (C41.D37F), SUSH2A_ADC_DAC_BIO (C147.D9M)
SUS_HAM2_048: MC1 and MC3 Top Masses (C41.D37M), SUSH2A_ADC_DAC_BIO (C151.D9F)
SUS_HAM2_049: PRM and PR3 Top Masses (C83.D37F), SUSH2A_ADC_DAC_BIO (C147.D9M)
SUS_HAM2_050: PRM and PR3 Top Masses (C83.D37M), SUSH2A_ADC_DAC_BIO (C151.D9F)
SUS_HAM2_051: PRM and PR3 Top Masses (C88.D37F), SUSH2A_ADC_DAC_BIO (C153.D9F)
SUS_HAM2_052: PRM and PR3 Top Masses (C88.D37M), SUSH2A_ADC_DAC_BIO (C157.D9F)
SUS_HAM2_053: PRM and PR3 Top Masses (C94.D37F), SUSH2A_ADC_DAC_BIO (C153.D9F)
SUS_HAM2_054: PRM and PR3 Top Masses (C94.D37M), SUSH2A_ADC_DAC_BIO (C157.D9F)
SUS_HAM2_055: MC1 Middle and Bottom (C47.D25F), SUSH2A_ADC_DAC_BIO (C135.D25M)
SUS_HAM2_056: MC1 Middle and Bottom (C47.D25M), SUSH2A_ADC_DAC_BIO (C141.D25F)
SUS_HAM2_057: MC1 Middle and Bottom (C53.D25F), SUSH2A_ADC_DAC_BIO (C135.D25M)
SUS_HAM2_058: MC1 Middle and Bottom (C53.D25M), SUSH2A_ADC_DAC_BIO (C141.D25F)
SUS_HAM2_059: MC3 Middle and Bottom (C59.D25F), SUSH2A_ADC_DAC_BIO (C135.D25M)
SUS_HAM2_060: MC3 Middle and Bottom (C59.D25M), SUSH2A_ADC_DAC_BIO (C141.D25F)
SUS_HAM2_061: MC3 Middle and Bottom (C65.D25F), SUSH2A_ADC_DAC_BIO (C135.D25M)
SUS_HAM2_062: MC3 Middle and Bottom (C65.D25M), SUSH2A_ADC_DAC_BIO (C141.D25F)
SUS_HAM2_063: PRM Middle and Bottom (C100.D25F), SUSH2A_ADC_DAC_BIO (C147.D25M)
SUS_HAM2_064: PRM Middle and Bottom (C100.D25M), SUSH2A_ADC_DAC_BIO (C151.D25F)
SUS_HAM2_065: PRM Middle and Bottom (C106.D25F), SUSH2A_ADC_DAC_BIO (C147.D25M)
SUS_HAM2_066: PRM Middle and Bottom (C106.D25M), SUSH2A_ADC_DAC_BIO (C151.D25F)
SUS_HAM2_067: PR3 Middle and Bottom (C71.D25F), SUSH2A_ADC_DAC_BIO (C147.D25M)
SUS_HAM2_068: PR3 Middle and Bottom (C71.D25M), SUSH2A_ADC_DAC_BIO (C151.D25F)
SUS_HAM2_069: PR3 Middle and Bottom (C77.D25F), SUSH2A_ADC_DAC_BIO (C147.D25M)
SUS_HAM2_070: PR3 Middle and Bottom (C77.D25M), SUSH2A_ADC_DAC_BIO (C151.D25F)
SUS_HAM2_071: MC1 and MC3 Top Masses (C30.D9F), SUSH2A_ADC_DAC_BIO (C136.D9M)
SUS_HAM2_072: MC1 and MC3 Top Masses (C35.D9F), SUSH2A_ADC_DAC_BIO (C136.D9M)
SUS_HAM2_073: MC1 and MC3 Top Masses (C41.D9F), SUSH2A_ADC_DAC_BIO (C136.D9M)
SUS_HAM2_074: PRM and PR3 Top Masses (C83.D9F), SUSH2A_ADC_DAC_BIO (C136.D9M)
SUS_HAM2_075: PRM and PR3 Top Masses (C88.D9F), SUSH2A_ADC_DAC_BIO (C136.D9M)
SUS_HAM2_076: PRM and PR3 Top Masses (C94.D9F), SUSH2A_ADC_DAC_BIO (C136.D9M)
SUS_HAM2_077: MC1 Middle and Bottom (C47.D9F), SUSH2A_ADC_DAC_BIO (C136.D9M)
SUS_HAM2_081: MC1 Middle and Bottom (C53.D9F), SUSH2A_ADC_DAC_BIO (C142.D9M)
SUS_HAM2_082: MC3 Middle and Bottom (C59.D9F), SUSH2A_ADC_DAC_BIO (C142.D9M)
SUS_HAM2_083: MC3 Middle and Bottom (C65.D9F), SUSH2A_ADC_DAC_BIO (C142.D9M)
SUS_HAM2_084: PRM Middle and Bottom (C100.D9F), SUSH2A_ADC_DAC_BIO (C142.D9M)
SUS_HAM2_085: PRM Middle and Bottom (C106.D9F), SUSH2A_ADC_DAC_BIO (C142.D9M)
SUS_HAM2_086: PR3 Middle and Bottom (C71.D9F), SUSH2A_ADC_DAC_BIO (C142.D9M)
SUS_HAM2_087: PR3 Middle and Bottom (C77.D9F), SUSH2A_ADC_DAC_BIO (C142.D9M)
SUS_HAM2_091: MC1 and MC3 Top Masses (C30.D9M), SUSH2A_ADC_DAC_BIO (C137.D9F)
SUS_HAM2_092: MC1 and MC3 Top Masses (C35.D9M), SUSH2A_ADC_DAC_BIO (C137.D9F)
SUS_HAM2_093: MC1 and MC3 Top Masses (C41.D9M), SUSH2A_ADC_DAC_BIO (C137.D9F)
SUS_HAM2_094: PRM and PR3 Top Masses (C83.D9M), SUSH2A_ADC_DAC_BIO (C137.D9F)
SUS_HAM2_098: PRM and PR3 Top Masses (C88.D9M), SUSH2A_ADC_DAC_BIO (C145.D9F)
SUS_HAM2_099: PRM and PR3 Top Masses (C94.D9M), SUSH2A_ADC_DAC_BIO (C145.D9F)
SUS_HAM2_100: MC1 Middle and Bottom (C47.D9M), SUSH2A_ADC_DAC_BIO (C145.D9F)
SUS_HAM2_101: MC1 Middle and Bottom (C53.D9M), SUSH2A_ADC_DAC_BIO (C145.D9F)
SUS_HAM2_105: MC3 Middle and Bottom (C59.D9M), SUSH2A_ADC_DAC_BIO (C150.D9F)
SUS_HAM2_106: MC3 Middle and Bottom (C65.D9M), SUSH2A_ADC_DAC_BIO (C150.D9F)
SUS_HAM2_107: PRM Middle and Bottom (C100.D9M), SUSH2A_ADC_DAC_BIO (C150.D9F)
SUS_HAM2_108: PRM Middle and Bottom (C106.D9M), SUSH2A_ADC_DAC_BIO (C150.D9F)
SUS_HAM2_112: PR3 Middle and Bottom (C71.D9M), SUSH2A_ADC_DAC_BIO (C155.D9F)
SUS_HAM2_113: PR3 Middle and Bottom (C77.D9M), SUSH2A_ADC_DAC_BIO (C155.D9F)
SUS_HAM2_119: MC1 and MC3 Top Masses (C30.D9F), SUSAUXH2_ADC_Monitors (C133.D9M)
SUS_HAM2_120: MC1 and MC3 Top Masses (C35.D9F), SUSAUXH2_ADC_Monitors (C133.D9M)
SUS_HAM2_121: MC1 and MC3 Top Masses (C30.D25M), SUSAUXH2_ADC_Monitors (C133.D25M)
SUS_HAM2_122: MC1 and MC3 Top Masses (C35.D25M), SUSAUXH2_ADC_Monitors (C133.D25M)
SUS_HAM2_125: MC1 and MC3 Top Masses (C41.D9F), SUSAUXH2_ADC_Monitors (C121.D9M)
SUS_HAM2_126: PRM and PR3 Top Masses (C83.D9F), SUSAUXH2_ADC_Monitors (C121.D9M)
SUS_HAM2_127: MC1 and MC3 Top Masses (C41.D25M), SUSAUXH2_ADC_Monitors (C121.D25M)
SUS_HAM2_128: PRM and PR3 Top Masses (C83.D25M), SUSAUXH2_ADC_Monitors (C121.D25M)
SUS_HAM2_131: PRM and PR3 Top Masses (C88.D9F), SUSAUXH2_ADC_Monitors (C123.D9M)
SUS_HAM2_132: PRM and PR3 Top Masses (C94.D9F), SUSAUXH2_ADC_Monitors (C123.D9M)
SUS_HAM2_133: PRM and PR3 Top Masses (C88.D25M), SUSAUXH2_ADC_Monitors (C123.D25M)
SUS_HAM2_134: PRM and PR3 Top Masses (C94.D25M), SUSAUXH2_ADC_Monitors (C123.D25M)
SUS_HAM2_137: MC1 Middle and Bottom (C47.D9F), SUSAUXH2_ADC_Monitors (C125.D9M)
SUS_HAM2_138: MC1 Middle and Bottom (C53.D9F), SUSAUXH2_ADC_Monitors (C125.D9M)
SUS_HAM2_139: MC1 Middle and Bottom (C47.D25M), SUSAUXH2_ADC_Monitors (C125.D25M)
SUS_HAM2_140: MC1 Middle and Bottom (C53.D25M), SUSAUXH2_ADC_Monitors (C125.D25M)
SUS_HAM2_143: MC3 Middle and Bottom (C59.D9F), SUSAUXH2_ADC_Monitors (C127.D9M)
SUS_HAM2_144: MC3 Middle and Bottom (C65.D9F), SUSAUXH2_ADC_Monitors (C127.D9M)
SUS_HAM2_145: MC3 Middle and Bottom (C59.D25M), SUSAUXH2_ADC_Monitors (C127.D25M)
SUS_HAM2_146: MC3 Middle and Bottom (C65.D25M), SUSAUXH2_ADC_Monitors (C127.D25M)
SUS_HAM2_149: PRM Middle and Bottom (C100.D9F), SUSAUXH2_ADC_Monitors (C129.D9M)
SUS_HAM2_150: PRM Middle and Bottom (C106.D9F), SUSAUXH2_ADC_Monitors (C129.D9M)
SUS_HAM2_151: PRM Middle and Bottom (C100.D25M), SUSAUXH2_ADC_Monitors (C129.D25M)
SUS_HAM2_152: PRM Middle and Bottom (C106.D25M), SUSAUXH2_ADC_Monitors (C129.D25M)
SUS_HAM2_155: PR3 Middle and Bottom (C71.D9F), SUSAUXH2_ADC_Monitors (C131.D9M)
SUS_HAM2_156: PR3 Middle and Bottom (C77.D9F), SUSAUXH2_ADC_Monitors (C131.D9M)
SUS_HAM2_157: PR3 Middle and Bottom (C71.D25M), SUSAUXH2_ADC_Monitors (C131.D25M)
SUS_HAM2_158: PR3 Middle and Bottom (C77.D25M), SUSAUXH2_ADC_Monitors (C131.D25M)
SUS_HAM2_161: IM1_IM2_IM3_IM4_OSEMs (C6.D9F), SUSH2B_ADC_DAC_BIO (C160.D9M)
SUS_HAM2_163: IM1_IM2_IM3_IM4_OSEMs (C24.D9F), SUSH2B_ADC_DAC_BIO (C160.D9M)
SUS_HAM2_166: IM1_IM2_IM3_IM4_OSEMs (C6.D9M), SUSH2B_ADC_DAC_BIO (C162.D9F)
SUS_HAM2_167: IM1_IM2_IM3_IM4_OSEMs (C24.D9M), SUSH2B_ADC_DAC_BIO (C162.D9F)
SUS_HAM2_174: IM1_IM2_IM3_IM4_OSEMs (C12.D9F), SUSH2B_ADC_DAC_BIO (C160.D9M)
SUS_HAM2_176: IM1_IM2_IM3_IM4_OSEMs (C18.D9F), SUSH2B_ADC_DAC_BIO (C160.D9M)
SUS_HAM2_179: IM1_IM2_IM3_IM4_OSEMs (C12.D9M), SUSH2B_ADC_DAC_BIO (C162.D9F)
SUS_HAM2_180: IM1_IM2_IM3_IM4_OSEMs (C18.D9M), SUSH2B_ADC_DAC_BIO (C162.D9F)
SUS_HAM2_235: IM1_IM2_IM3_IM4_OSEMs (C6.D9F), SUSAUXH2_ADC_Monitors (C118.D9M)
SUS_HAM2_236: IM1_IM2_IM3_IM4_OSEMs (C24.D9F), SUSAUXH2_ADC_Monitors (C118.D9M)
SUS_HAM2_237: IM1_IM2_IM3_IM4_OSEMs (C12.D9F), SUSAUXH2_ADC_Monitors (C118.D9M)
SUS_HAM2_238: IM1_IM2_IM3_IM4_OSEMs (C18.D9F), SUSAUXH2_ADC_Monitors (C118.D9M)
